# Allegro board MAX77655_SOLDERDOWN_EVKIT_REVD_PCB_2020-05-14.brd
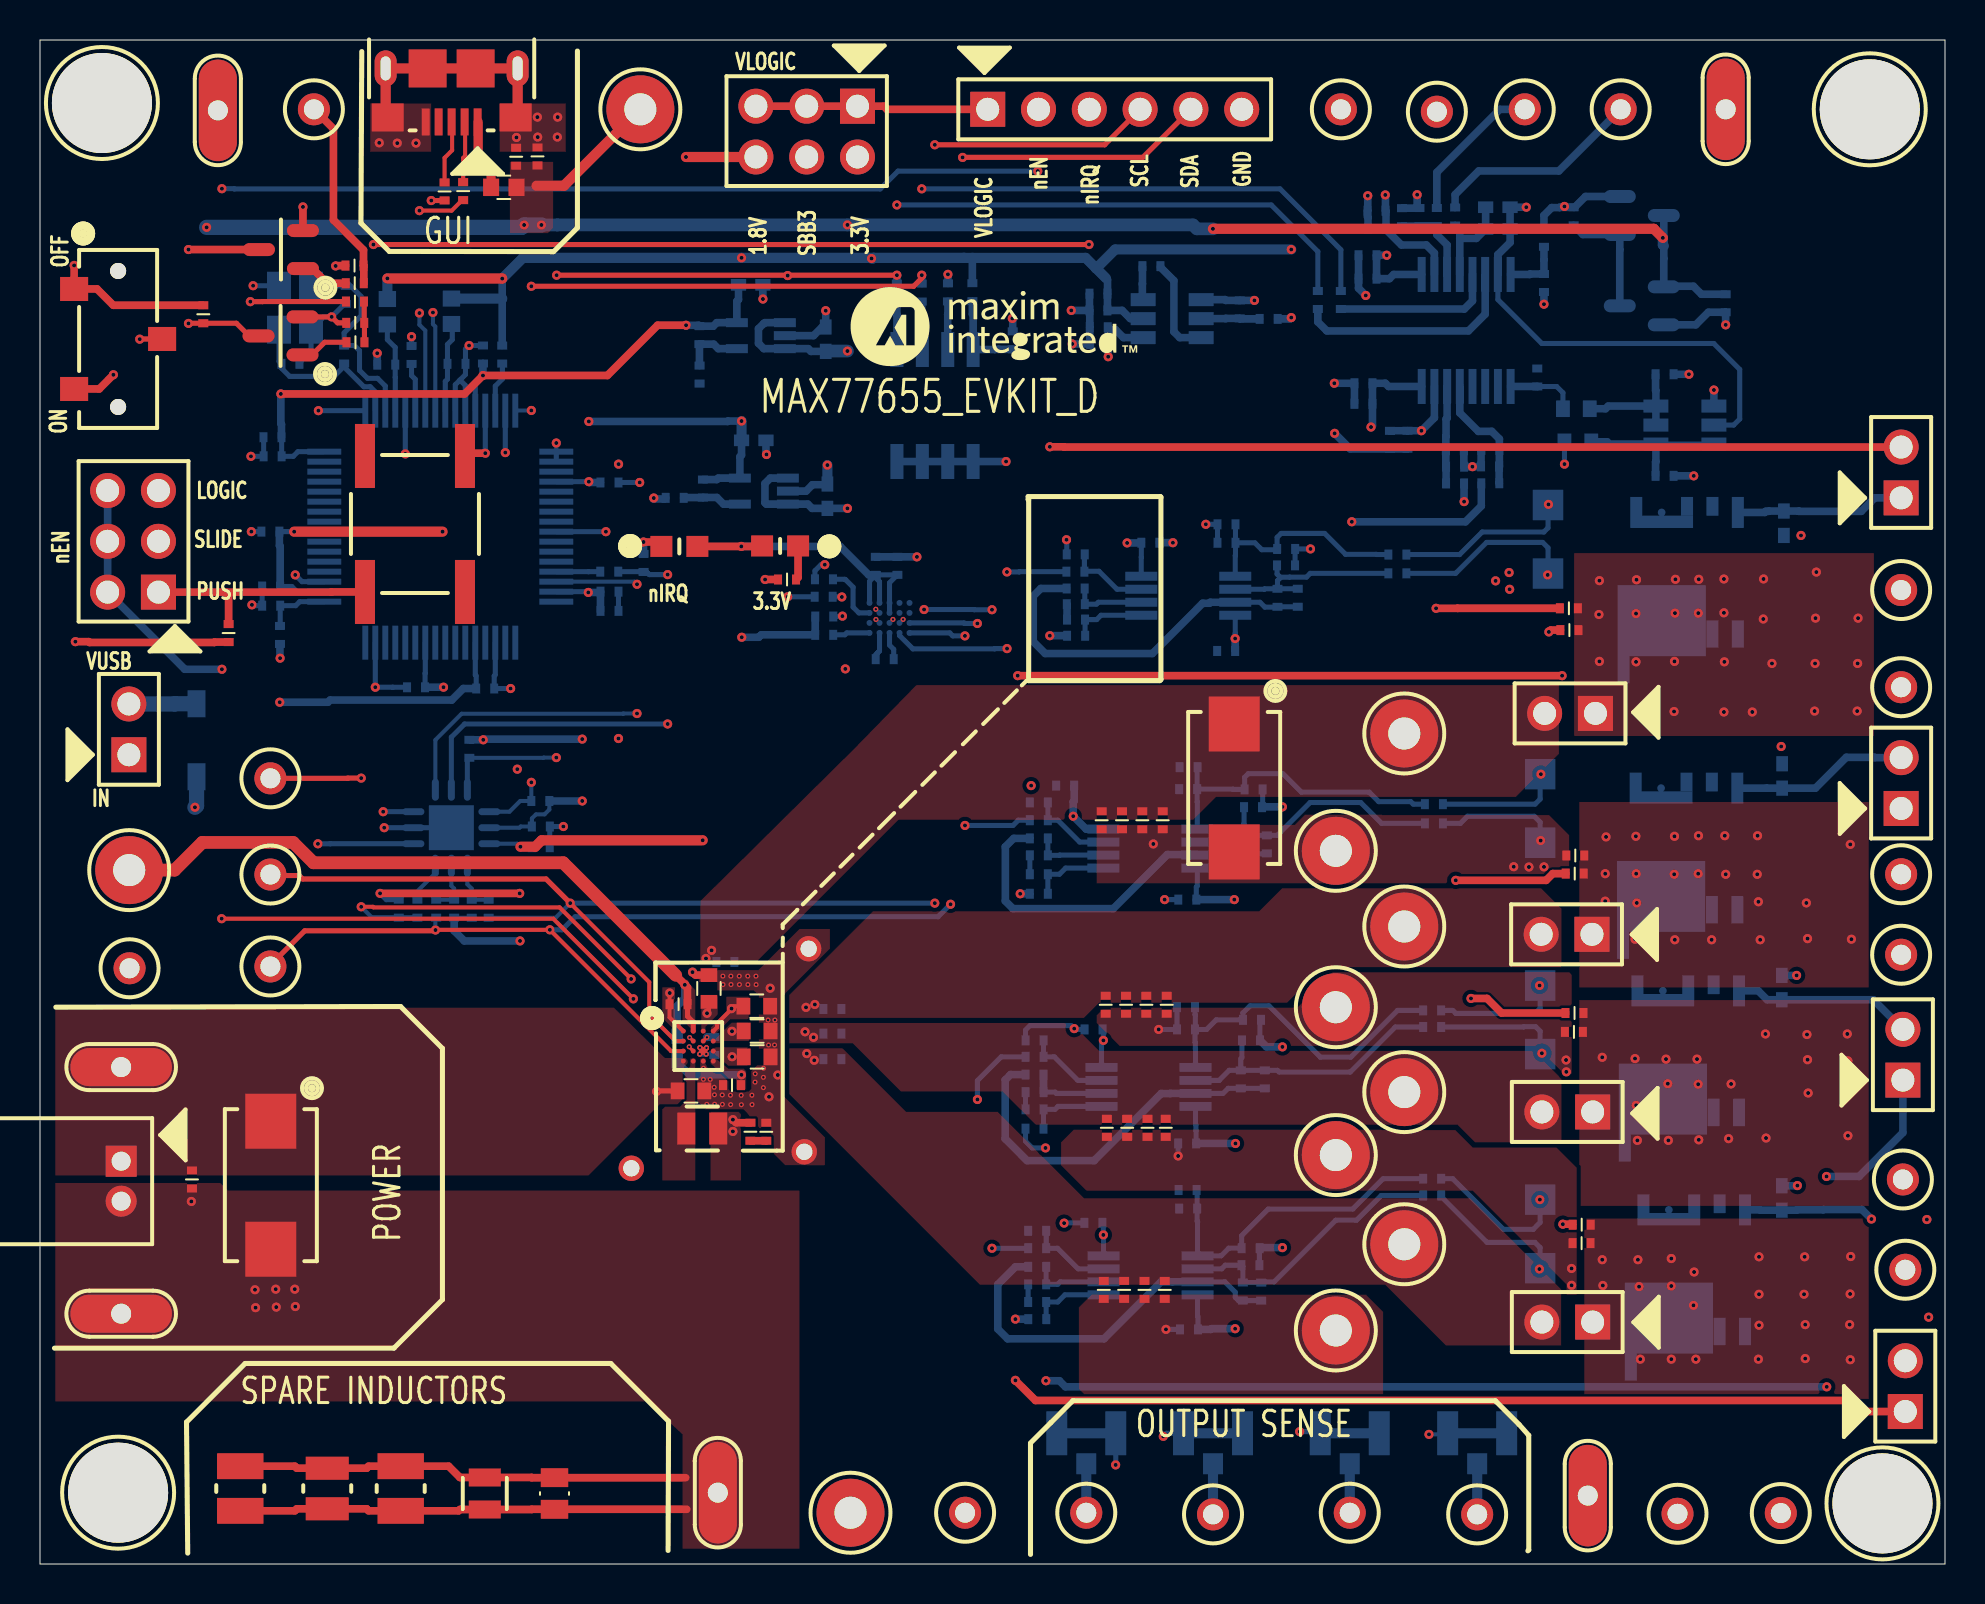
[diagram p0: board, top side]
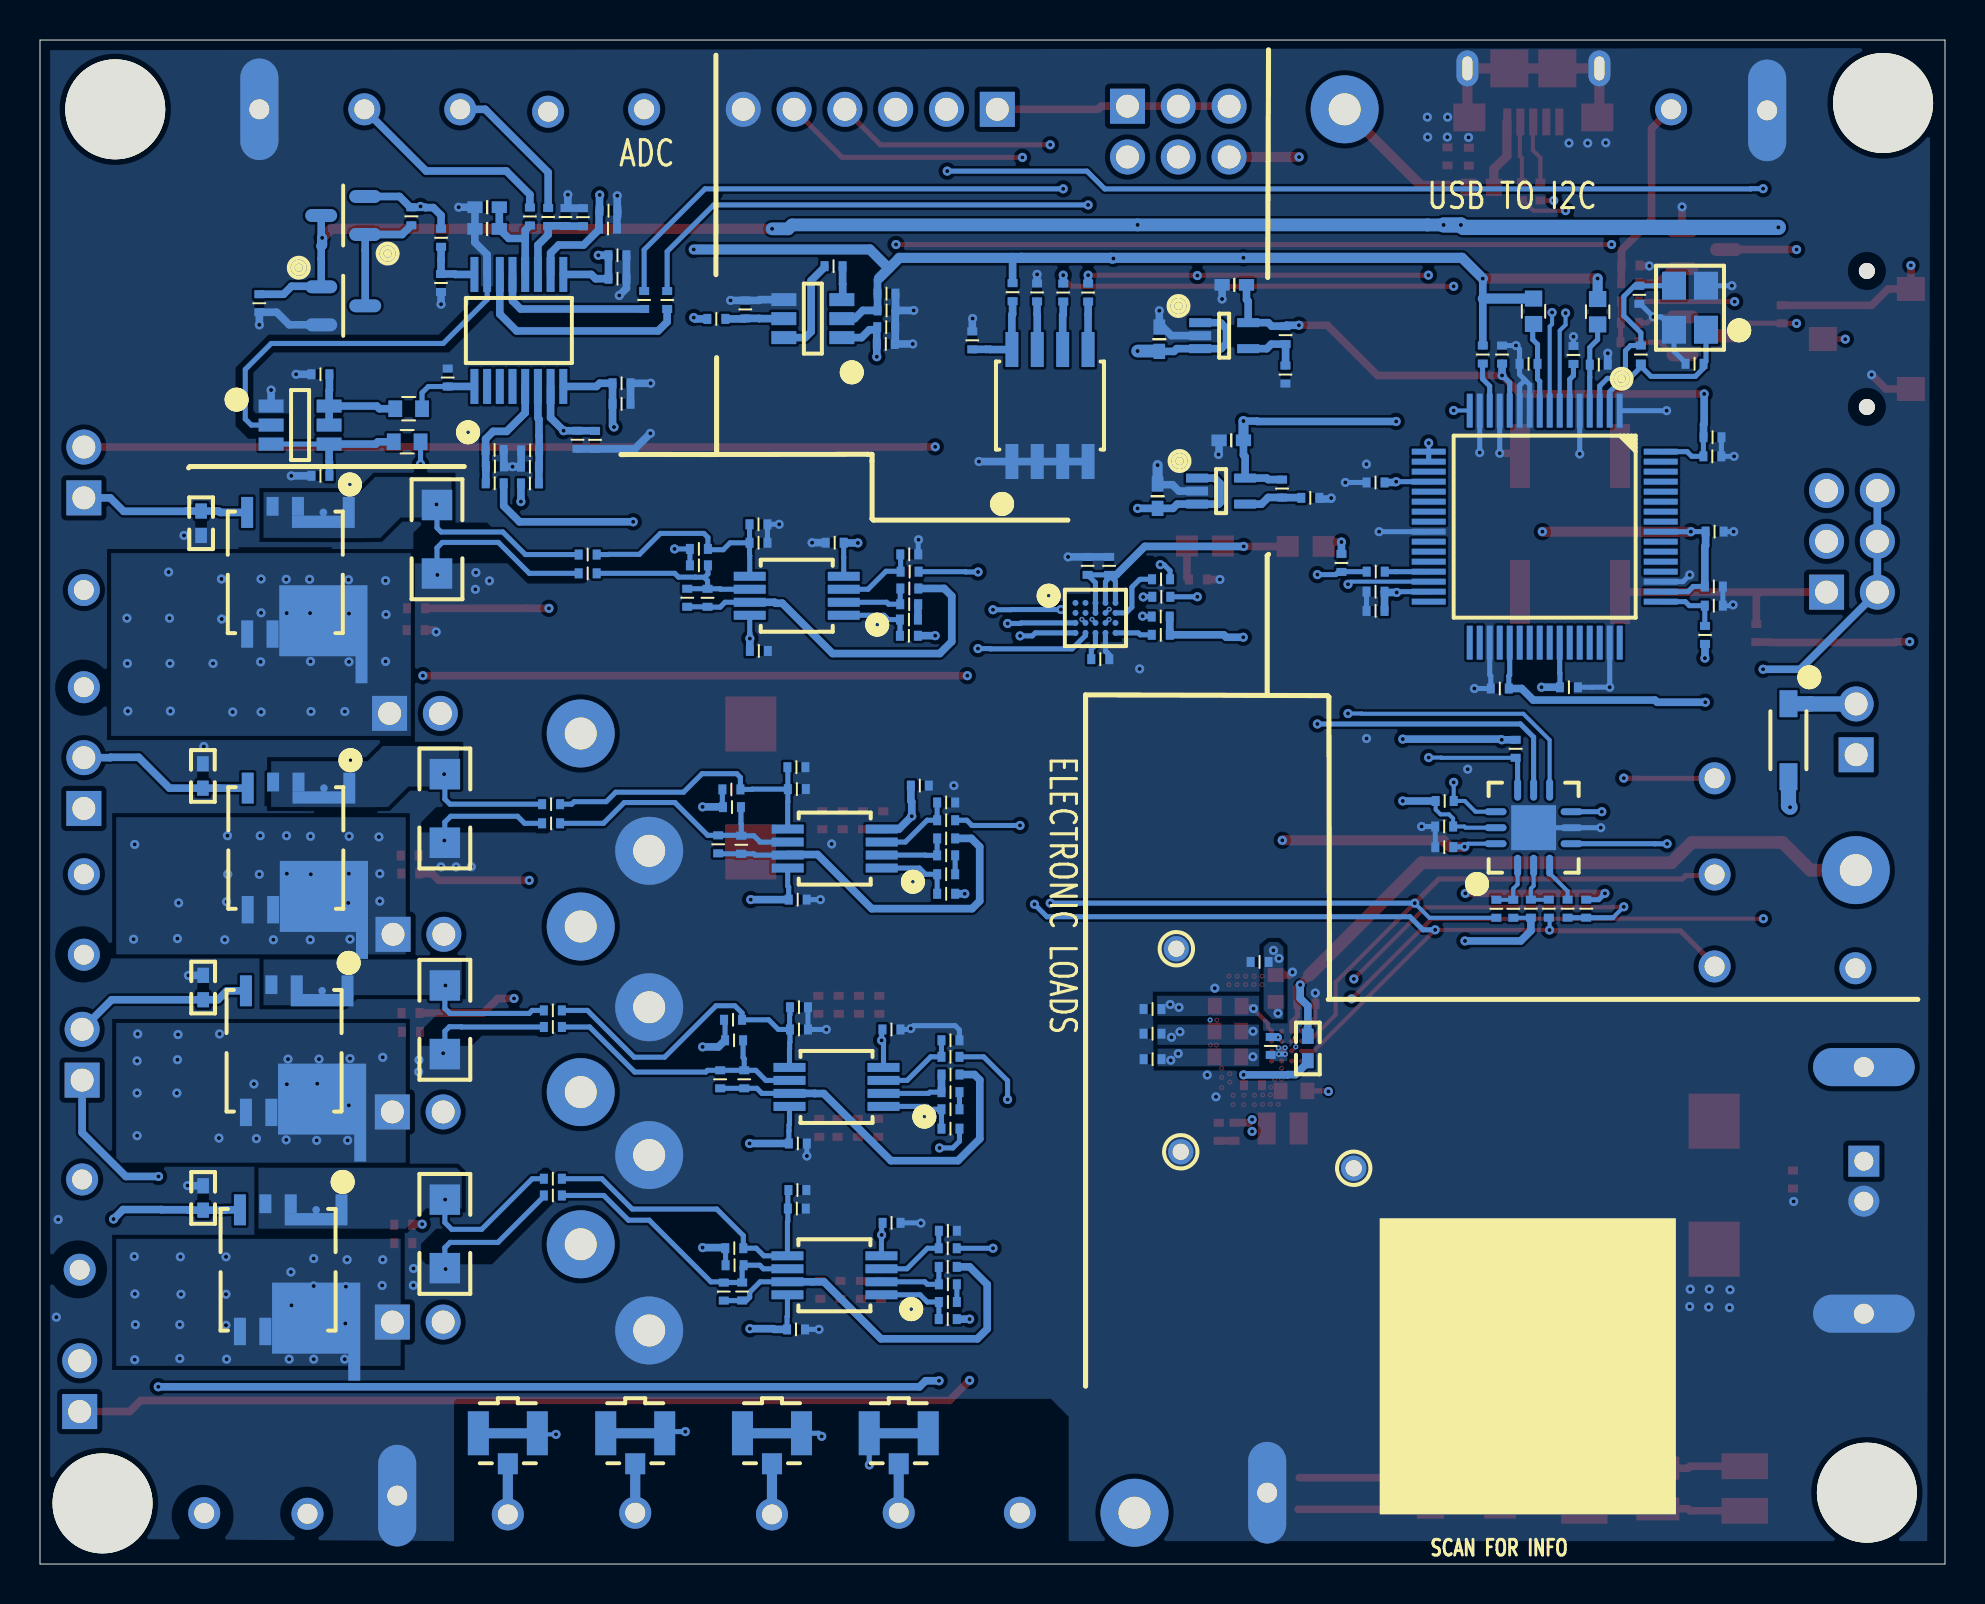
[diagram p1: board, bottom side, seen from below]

Outline 95.25 x 76.2 mm; copper layers: TOP, INTERNAL2, INTERNAL3, BOTTOM. Coordinates in mm from the lower left corner of the outline.
Outline path: 0,76.2 0,0 95.25,0 95.25,76.2 0,76.2

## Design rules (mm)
constraint set DEFAULT: min track width 0.102

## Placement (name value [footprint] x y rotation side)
AIN0  N/A  [KEYS_5002]  65.04 72.73 0 top
AIN1  N/A  [KEYS_5002]  69.84 72.61 0 top
AIN6  N/A  [KEYS_5002]  74.24 72.73 0 top
AIN7  N/A  [KEYS_5002]  79.03 72.73 0 top
B0_S  U.FL-R-SMT-1  [HRS_UFL-R-SMT-1]  71.86 6.54 180 bottom
B0_SNS  N/A  [KEYS_5000]  71.86 2.48 0 top
B1_S  U.FL-R-SMT-1  [HRS_UFL-R-SMT-1]  65.49 6.54 180 bottom
B1_SNS  N/A  [KEYS_5000]  65.49 2.56 0 top
B2_S  U.FL-R-SMT-1  [HRS_UFL-R-SMT-1]  58.65 6.54 180 bottom
B2_SNS  N/A  [KEYS_5000]  58.65 2.48 0 top
B3_S  U.FL-R-SMT-1  [HRS_UFL-R-SMT-1]  52.31 6.54 180 bottom
B3_SNS  N/A  [KEYS_5000]  52.31 2.56 0 top
C1  0.1UF  [0402]  7.6 19.23 90 top
C2  100UF  [CAPMP7343X430M]  11.54 18.94 270 top
C3  10UF  [0402]  34.6 23.94 0 top
C4  0.01UF  [0402]  33.71 25.9 270 bottom
C5  22UF  [CAPC1608X90L]  32.55 23.66 180 top
C6  22UF  [0603]  35.86 25.36 180 top
C7  4700PF  [0402]  72.52 55.7 0 bottom
C8  47UF  [0603]  35.85 26.65 180 top
C9  4700PF  [0402]  68.1 67.34 270 bottom
C10  1UF  [0402]  31.93 27.99 0 top
C11  47UF  [0603]  35.84 27.89 180 top
C12  100UF  [CAPMP7343X430M]  59.71 38.8 270 top
C13  OPEN  [CAPC1005X50L]  39.62 25.24 180 bottom
C14  22UF  [0603]  33.45 28.78 270 top
C15  OPEN  [CAPC1005X50L]  34.27 30.1 180 bottom
C16  1UF  [0402]  25.04 36.87 180 bottom
C17  OPEN  [CAPC1005X50L]  39.62 27.75 180 bottom
C18  OPEN  [CAPC1005X50L]  39.62 26.52 180 bottom
C19  1500PF  [0402]  36.31 21.61 270 top
C21  4.7UF  [0402]  24.87 70.38 270 top
C22  0.1UF  [0402]  23.81 70.36 270 top
C23  27PF  [0402]  12.52 60.01 180 bottom
C24  27PF  [0402]  15.28 63.46 90 bottom
C25  0.1UF  [0402]  11.56 48.88 0 bottom
C26  0.1UF  [0402]  17.31 59.97 0 bottom
C27  0.1UF  [0402]  20.82 60.01 180 bottom
C28  4.7UF  [0402]  11.56 47.92 0 bottom
C29  1UF  [0402#2]  39.29 61.24 270 bottom
C30  0.1UF  [0402]  22.15 60.47 270 bottom
C31  4.7UF  [0402]  28.47 47.65 180 bottom
C32  0.1UF  [0402]  11.63 55.38 0 bottom
C33  0.1UF  [0402]  11.52 51.62 0 bottom
C34  0.1UF  [0402]  11.62 56.34 0 bottom
C35  0.1UF  [0402]  18.8 43.84 0 bottom
C36  1UF  [0402#2]  35.53 63.96 180 bottom
C37  0.1UF  [0402]  22.26 43.77 180 bottom
C38  0.1UF  [0402]  28.47 48.62 180 bottom
C39  0.1UF  [0402]  28.47 54.08 180 bottom
C41  1UF  [0402#2]  39.37 53.39 270 bottom
C42  1UF  [0402#2]  35.69 56.18 180 bottom
C44  0.1UF  [0402]  25.04 35.84 180 bottom
C53  OPEN  [CAPC1005X50L]  53.34 21.81 90 top
C54  OPEN  [CAPC1005X50L]  53.19 13.71 90 top
C56  OPEN  [CAPC1005X50L]  53.08 37.19 90 top
C57  OPEN  [CAPC1005X50L]  53.29 27.96 90 top
C58  OPEN  [CAPC1005X50L]  54.36 21.81 90 top
C59  OPEN  [CAPC1005X50L]  54.21 13.71 90 top
C61  OPEN  [CAPC1005X50L]  54.1 37.19 90 top
C62  OPEN  [CAPC1005X50L]  54.3 27.96 90 top
C63  0.1UF  [CAPC1005X50L]  55.22 13.71 90 top
C65  0.1UF  [CAPC1005X50L]  55.12 37.19 90 top
C66  0.1UF  [CAPC1005X50L]  55.32 27.96 90 top
C67  0.1UF  [CAPC1005X50L]  55.37 21.81 90 top
C68  0.01UF  [CAPC1005X50L]  56.13 37.19 90 top
C69  0.01UF  [CAPC1005X50L]  56.24 13.71 90 top
C71  0.01UF  [CAPC1005X50L]  56.33 27.96 90 top
C72  0.01UF  [CAPC1005X50L]  56.29 21.81 90 top
C73  0.1UF  [0402]  48.64 61.18 270 bottom
C200  4700PF  [0402]  51.79 50.48 0 bottom
C201  0.01UF  [CAPC1005X50L]  51.79 47.99 180 bottom
C202  0.1UF  [CAPC1005X50L]  59.31 45.65 180 bottom
C203  1000PF  [0402]  61.87 48.31 90 bottom
C204  1000PF  [0402]  59.32 51.06 0 bottom
C205  4700PF  [0402]  68.38 56.21 90 bottom
C206  0.01UF  [CAPC1005X50L]  49.94 35.43 180 bottom
C207  0.1UF  [CAPC1005X50L]  57.36 33.22 180 bottom
C208  1000PF  [0402]  57.41 38.74 0 bottom
C209  1000PF  [0402]  61.34 35.98 90 bottom
C210  4700PF  [0402]  66.17 58.01 0 bottom
C211  0.01UF  [CAPC1005X50L]  49.73 23.59 180 bottom
C212  0.1UF  [CAPC1005X50L]  57.36 21.03 180 bottom
C213  1000PF  [0402]  60.04 24.23 90 bottom
C214  1000PF  [0402]  57.3 26.73 0 bottom
C215  4700PF  [0402]  66.38 65.44 0 bottom
C216  0.01UF  [CAPC1005X50L]  49.86 13.98 180 bottom
C217  0.1UF  [CAPC1005X50L]  57.45 11.73 180 bottom
C218  1000PF  [0402]  57.41 17.77 0 bottom
C219  1000PF  [0402]  60.14 13.62 90 bottom
C220  4700PF  [0402]  66.85 66.77 0 bottom
C221  0.1UF  [CAPC1005X50L]  41.79 49.91 270 bottom
C222  0.1UF  [CAPC1005X50L]  42.87 49.91 270 bottom
C223  0.1UF  [CAPC1005X50L]  42.24 45.24 0 bottom
C234  0.1UF  [0402]  81.23 54.41 180 bottom
C235  0.1UF  [0402]  81.23 59.49 180 bottom
C237  0.1UF  [CAPC1005X50L]  75.2 64.05 90 bottom
C238  4700PF  [0402#2]  72.89 67.84 180 bottom
C239  1UF  [CAPC1005X50L]  76.47 46.7 0 top
C240  1UF  [CAPC1005X50L]  76.76 35.42 0 top
C241  1UF  [CAPC1005X50L]  76.7 26.6 0 top
C242  1UF  [CAPC1005X50L]  77.08 16.04 0 top
C244  0.1UF  [CAPC1005X50L]  74.86 59.32 270 bottom
C248  4700PF  [0402]  49.94 38.08 0 bottom
C250  4700PF  [0402]  49.73 26.19 0 bottom
C251  4700PF  [0402]  49.86 16.66 0 bottom
C252  4700PF  [0402]  70.74 55.69 180 bottom
C268  0.1UF  [CAPC1005X50L]  52.93 63.52 0 bottom
C269  1UF  [CAPC1005X50L]  52.92 62.68 0 bottom
C270  1UF  [CAPC1005X50L]  55.57 64.89 0 bottom
C271  1UF  [CAPC1005X50L]  52.94 61.84 0 bottom
C272  0.1UF  [CAPC1005X50L]  52.96 61 0 bottom
C273  0.1UF  [CAPC1005X50L]  59.99 62.73 270 bottom
C274  0.1UF  [CAPC1005X50L]  55.52 51.06 180 bottom
C275  0.1UF  [CAPC1005X50L]  51.26 38.92 0 bottom
C276  0.1UF  [CAPC1005X50L]  52.68 26.73 0 bottom
C277  0.1UF  [CAPC1005X50L]  52.67 17.06 0 bottom
D1  B0530W  [SOD3718X145M]  7.83 41.19 270 bottom
DS1  LTST-C190CKT  [LEDC1608X80M]  31.97 50.88 0 top
DS2  LTST-C190CKT  [LEDC1608X80M]  37 50.9 180 top
GND1  N/A  [KEYS_5011]  64.79 27.84 0 top
GND2  MAXIMPAD  [EVK_MAXIMPAD]  4.06 12.51 180 top
GND3  MAXIMPAD  [EVK_MAXIMPAD]  8.89 72.68 90 top
GND4  MAXIMPAD  [EVK_MAXIMPAD]  84.28 72.73 270 top
GND5  N/A  [KEYS_5011]  64.79 35.66 0 top
GND6  N/A  [KEYS_5011]  64.79 20.45 0 top
GND7  N/A  [KEYS_5011]  64.79 11.68 0 top
GND8  MAXIMPAD  [EVK_MAXIMPAD]  77.39 3.42 90 top
GND10  MAXIMPAD  [EVK_MAXIMPAD]  33.89 3.57 90 top
GND_SNS  N/A  [KEYS_5001]  46.25 2.56 0 top
GNDS1  NA  [TP_C127H81]  29.57 19.79 180 bottom
GNDS2  NA  [TP_C127H81]  38.43 30.76 180 bottom
GNDS3  NA  [TP_C127H81]  38.21 20.61 180 bottom
GNDS_SBB0  N/A  [KEYS_5001]  93.06 43.84 0 top
GNDS_SBB1  N/A  [KEYS_5001]  93.06 30.46 0 top
GNDS_SBB2  N/A  [KEYS_5001]  93.27 14.71 0 top
GNDS_SBB3  N/A  [KEYS_5001]  81.88 2.51 0 top
IN  MAXIMPAD  [EVK_MAXIMPAD]  4.06 24.85 0 top
IN_SNS  N/A  [KEYS_5000]  4.48 29.79 0 top
J1  10118193-0001LF  [FCI_10118193-0001LF]  20.58 74.78 180 top
J2  PBC06SAAN  [SULLINS_PXC06SAAN]  47.39 72.73 0 top
J3  PBC03DAAN  [SULLINS_PXC03DAAN]  5.92 48.59 90 top
J4  PBC03DAAN  [SULLINS_PXC03DAAN]  40.87 72.89 180 top
J5  TSW-102-07-T-S  [SAMTEC_TSW-102-07-X-S]  4.44 40.46 90 top
J9  S2B-PH-K-S(LF)(SN)  [JST_S2B-PH-K-X]  4.06 20.14 90 top
J200  TSW-102-07-T-S  [SAMTEC_TSW-102-07-X-S]  93.06 53.31 90 top
J201  TSW-102-07-T-S  [SAMTEC_TSW-102-07-X-S]  77.77 42.53 180 top
J202  TSW-102-07-T-S  [SAMTEC_TSW-102-07-X-S]  93.06 37.78 90 top
J203  TSW-102-07-T-S  [SAMTEC_TSW-102-07-X-S]  77.6 31.48 180 top
J204  TSW-102-07-T-S  [SAMTEC_TSW-102-07-X-S]  93.14 24.19 90 top
J205  TSW-102-07-T-S  [SAMTEC_TSW-102-07-X-S]  77.63 22.6 180 top
J206  TSW-102-07-T-S  [SAMTEC_TSW-102-07-X-S]  93.27 7.62 90 top
J207  TSW-102-07-T-S  [SAMTEC_TSW-102-07-X-S]  77.63 12.1 180 top
L1  1.5UH  [IND_2016]  33.11 21.77 180 top
L2  600  [0603#2]  23.19 68.83 0 top
L3  1.5UH  [0805]  25.73 3.53 270 top
L4  600  [0603#2]  20.57 62.64 270 bottom
L5  600  [0603#2]  17.37 62.61 270 bottom
L6  1.5UH  [IND_2016]  22.24 3.53 90 top
L7  1UH  [INDC2520X120M]  18.03 3.77 90 top
L8  2.2UH  [IND_2520]  14.36 3.77 270 top
L9  2.2UH  [INDC2520X120M]  10.01 3.77 270 top
NEN_EXT  N/A  [KEYS_5002]  13.69 72.73 0 top
NIRQ  N/A  [KEYS_5002]  11.52 39.28 0 top
NOREF  -  []  12.7 -12.7 0 top
NOREF#2  -  [unnamed#2]  3.91 3.57 0 top
NOREF#3  -  [unnamed#2]  92.12 3.03 0 top
NOREF#4  -  [unnamed#2]  3.1 73.05 0 top
NOREF#5  -  []  38.94 48.61 0 top
NOREF#6  -  []  42.55 61.79 0 top
NOREF#7  -  []  0 76.2 0 top
NOREF#8  -  []  45.62 129.01 0 top
NOREF#9  -  []  0 0 90 top
NOREF#10  -  [unnamed#2]  91.49 72.73 0 top
NOREF#11  -  []  28.26 2.48 180 bottom
PVDD  N/A  [KEYS_5010]  40.53 2.56 0 top
Q1  BSS138  [SOT95P237X112-3M]  12.03 61.41 180 top
Q2  BSS138  [SOT95P237X112-3M]  12.05 65.72 180 top
Q200  IPC100N04S5L1R1ATMA1  [TRANS_PG-TDSON-8-34]  82.99 49.58 0 bottom
Q201  IPC100N04S5L1R1ATMA1  [TRANS_PG-TDSON-8-34]  82.96 35.8 0 bottom
Q202  IPC100N04S5L1R1ATMA1  [TRANS_PG-TDSON-8-34]  83.05 25.66 0 bottom
Q203  IPC100N04S5L1R1ATMA1  [TRANS_PG-TDSON-8-34]  83.35 14.71 0 bottom
Q205  FDN360P  [SOT95P237X112-3M]  80.09 67.43 0 bottom
Q206  2N7002  [SOT95P237X112-3M]  80.09 62.91 180 bottom
R1  0  [RESC1005X50L]  72.51 54.03 0 bottom
R2  10K  [0402]  69.84 67.35 270 bottom
R3  10M  [0402]  15.76 62.06 180 top
R4  1M  [0402]  72.5 54.88 180 bottom
R5  100K  [RESC1005X50L]  17.94 32.77 270 bottom
R6  10K  [0402]  68.98 67.35 90 bottom
R7  1  [0402]  15.77 61.09 180 top
R8  10M  [0402]  8.16 62.49 270 top
R9  0  [0402#2]  31.86 25.78 90 bottom
R10  27  [0402]  21.16 68.64 270 top
R11  27  [0402]  20.23 68.63 270 top
R12  12K  [0402]  18.58 60.45 270 bottom
R13  1M  [0402]  15.21 60.47 90 bottom
R14  1K  [0402]  23.11 60.47 270 bottom
R15  OPEN  [RESC1005X50L]  12 46.45 90 bottom
R16  47.5K  [0402]  32.97 61.44 270 bottom
R17  100K  [0402]  32.98 59.47 270 bottom
R18  150  [0402]  30.18 50.05 270 bottom
R19  0  [0402]  28.46 49.62 0 bottom
R20  0  [0402]  46.62 63.59 270 bottom
R21  4.7K  [0402]  21.47 40.76 270 bottom
R22  4.7K  [0402]  25.02 38.15 180 bottom
R23  169K  [0402]  33.15 53.77 270 bottom
R24  100K  [0402]  31.73 53.31 180 bottom
R25  2.2K  [0402]  20.71 32.77 90 bottom
R26  2.2K  [0402]  21.59 32.76 90 bottom
R27  22  [0402]  18.87 32.77 270 bottom
R28  470  [0402]  37.35 49.23 180 top
R29  0  [0402]  22.43 32.76 270 bottom
R30  0  [0402]  19.81 32.77 270 bottom
R31  0  [0402]  15.75 63.12 0 top
R32  1  [0402]  15.74 64.04 0 top
R33  10M  [0402]  15.73 64.92 180 top
R34  3.9  [0402]  35.52 21.61 270 top
R37  OPEN  [RESC1005X50L]  9.43 46.55 90 top
R52  0  [0402]  45.4 63.58 270 bottom
R53  0  [0402]  44.09 63.57 90 bottom
R54  0  [0402]  42.84 63.57 90 bottom
R201  100  [0402]  51.8 47.22 0 bottom
R202  680  [0402]  51.78 48.78 180 bottom
R203  20K  [0402]  51.77 49.62 0 bottom
R204  0  [RESC1005X50L]  51.81 46.41 180 bottom
R205  20K  [0402]  62.89 48.31 90 bottom
R206  20K  [0402]  59.33 51.98 0 bottom
R207  1K  [RESC1005X50L]  67.87 50.47 0 bottom
R208  1K  [RESC1005X50L]  67.87 49.53 0 bottom
R210  1M  [0402#2]  87.19 52.04 270 bottom
R211  0.1  [1206]  75.4 51.24 270 bottom
R212  787K  [0402]  76.45 47.78 180 top
R213  787K  [0402]  67.5 56.21 270 bottom
R214  100K  [RESC1005X50L]  39.21 47.37 0 bottom
R222  100  [0402]  49.94 34.49 0 bottom
R223  680  [0402]  49.94 36.28 180 bottom
R224  20K  [0402]  49.94 37.19 0 bottom
R225  0  [RESC1005X50L]  49.94 33.51 180 bottom
R226  20K  [0402]  57.43 39.84 0 bottom
R227  787K  [0402]  76.74 34.52 180 top
R228  20K  [0402]  60.19 35.96 90 bottom
R229  1K  [RESC1005X50L]  69.7 37.99 0 bottom
R230  1K  [RESC1005X50L]  69.7 37.03 0 bottom
R231  1M  [0402#2]  87.11 39.4 90 bottom
R233  0.1  [1206]  75.01 37.78 270 bottom
R234  787K  [0402]  66.17 59.04 180 bottom
R235  100  [0402]  49.73 22.74 0 bottom
R236  680  [0402]  49.72 24.47 180 bottom
R237  20K  [0402]  49.73 25.36 0 bottom
R238  0  [RESC1005X50L]  49.73 21.77 180 bottom
R239  20K  [0402]  61.24 24.23 90 bottom
R240  20K  [0402]  57.3 27.84 0 bottom
R242  1K  [RESC1005X50L]  69.61 27.68 0 bottom
R243  1K  [RESC1005X50L]  69.61 26.85 0 bottom
R244  1M  [0402#2]  87.09 28.82 90 bottom
R245  0.1  [1206]  75.01 27.21 270 bottom
R246  787K  [0402]  76.73 27.55 180 top
R247  787K  [0402]  66.38 64.26 180 bottom
R248  100  [0402]  49.86 13.1 0 bottom
R249  680  [0402]  49.86 14.86 180 bottom
R250  20K  [0402]  49.86 15.79 0 bottom
R251  0  [RESC1005X50L]  49.86 12.24 180 bottom
R252  20K  [0402]  57.38 18.7 0 bottom
R253  20K  [0402]  61.06 13.62 90 bottom
R254  1K  [RESC1005X50L]  69.61 19.26 0 bottom
R255  1K  [RESC1005X50L]  69.61 18.43 0 bottom
R257  1M  [0402#2]  87.09 18.3 90 bottom
R258  0.1  [1206]  75.01 16.51 270 bottom
R259  787K  [0402]  77.09 16.97 180 top
R260  787K  [0402]  66.82 67.67 180 bottom
R277  0  [RESC1608X90L]  76.89 56.11 0 bottom
R279  0  [RESC1608X90L]  76.82 57.76 180 bottom
R281  10K  [0402]  70.76 67.38 270 bottom
R282  10K  [0402#2]  72.9 66.75 0 bottom
R283  100K  [RESC1005X50L]  39.21 46.46 0 bottom
R286  0  [RESC1005X50L]  75.2 66.31 270 bottom
R287  10K  [0402]  84.28 63.04 270 bottom
R288  10K  [0402]  76.68 67.38 270 bottom
R289  100  [0402]  61.43 62.25 180 bottom
R293  470K  [0402]  62.31 50.75 0 bottom
R294  649K  [0402]  62.3 49.93 180 bottom
R295  470K  [0402]  60.68 38.73 0 bottom
R296  649K  [0402]  60.65 37.84 180 bottom
R297  470K  [0402]  60.6 27.21 0 bottom
R298  649K  [0402]  60.55 26.19 180 bottom
R299  470K  [0402]  60.54 15.79 0 bottom
R300  649K  [0402]  60.52 14.94 180 bottom
R301  1M  [0402]  70.76 54.87 0 bottom
R302  0  [RESC1005X50L]  70.75 54.03 180 bottom
R303  0  [RESC1005X50L]  63.89 63.2 270 bottom
R304  0  [RESC1005X50L]  65.04 63.2 270 bottom
R305  0  [RESC1005X50L]  39.18 48.36 0 bottom
R306  0  [RESC1005X50L]  39.2 49.24 0 bottom
SBB0  N/A  [KEYS_5010]  68.21 41.53 0 top
SBB1  N/A  [KEYS_5010]  68.21 31.87 0 top
SBB2  N/A  [KEYS_5010]  68.21 23.59 0 top
SBB3  N/A  [KEYS_5010]  68.21 15.99 0 top
SCL  N/A  [KEYS_5002]  11.52 34.47 0 top
SDA  N/A  [KEYS_5002]  11.52 29.88 0 top
SW1  EVQ-Q2K03W  [SW_EVQ-Q2X03W]  18.75 52 90 top
SW2  CL-SB-12B-11  [SW_CL-SB-12B-1X]  3.91 61.25 0 top
U1  MAX77655AEWE+  [MAXIM_21-100374]  32.91 25.9 0 top
U2  FT2232HL  [QFP50P1200X1200X160-64M]  20.02 51.87 270 bottom
U3  MAX8512EXK  [SOT65P210X110-5M]  36.04 61.42 180 bottom
U4  MAX8512EXK  [SOT65P210X110-5M]  36.2 53.64 180 bottom
U5  MAX3395EETC  [QFN80P400X400X80-13M]  20.57 36.82 90 bottom
U7  AT24CS02-SSHM  [SOIC127P600X175-8M]  44.75 57.92 90 bottom
U200  MAX44251AUA+  [SOP65P490X110-8M]  57.41 48.41 0 bottom
U201  MAX44251AUA+  [SOP65P490X110-8M]  55.51 35.77 0 bottom
U202  MAX44251AUA+  [SOP65P490X110-8M]  55.43 23.85 0 bottom
U203  MAX44251AUA+  [SOP65P490X110-8M]  55.53 14.44 0 bottom
U205  MAX5825AWP+T  [BGA20C50P5X4_250X225X64]  42.48 47.3 180 bottom
U209  MAX11614EEE+  [SOP63P600X175-16M]  71.31 61.68 90 bottom
U210  MAX6071AAUT41+  [SOT95P280X145-6M]  82.25 56.95 180 bottom
U211  MAX1697UEUT+  [SOT95P280X145-6M]  56.61 62.27 0 bottom
VDD  N/A  [KEYS_5010]  4.46 34.69 0 top
VIL_SBB0  N/A  [KEYS_5002]  93.06 48.7 0 top
VIL_SBB1  N/A  [KEYS_5002]  93.06 34.49 0 top
VIL_SBB2  N/A  [KEYS_5002]  93.14 19.23 0 top
VIL_SBB3  N/A  [KEYS_5002]  87.04 2.55 0 top
VUSB  N/A  [KEYS_5010]  30.02 72.73 0 top
Y1  12MHZ  [XTAL320X250X080M]  12.75 62.81 90 bottom

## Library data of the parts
AIN0 AIN1 AIN6 AIN7 NEN_EXT NIRQ SCL SDA VIL_SBB0-VIL_SBB3 = TP: part number: TP_TP-KEYS_5002,N/A,02-TPMINI5002-00
B0_S B1_S B2_S B3_S = UFL-R-SMT-1: part number: UFL-R-SMT-1_SMD-HRS_UFL-R-SMT-1,U.FL-R-SMT-1,01-UFLRSMT12P-10
B0_SNS B1_SNS B2_SNS B3_SNS IN_SNS = TP: part number: TP_TP-KEYS_5000,N/A,02-TPMINI5000-00
C1 C234 C235 = CAP_NP: alternate symbols: 0402_NOSILK,CAPC1005X50L,CAP0402-NOT_FOR_TEST; part number: CAP_NP_0402CAP-0402,0.1UF,20-000U1-E2A
C2 = CAP_POL: part number: CAP_POL_7343CAP-CAPMP7343X430M,100UF,20-0100U-P2
C3 = CAP_NP: alternate symbols: 0402_NOSILK,CAPC1005X50L,CAP0402-NOT_FOR_TEST; part number: CAP_NP_0402CAP-0402,10UF,20-0010U-BA12
C4 = CAP_NP: alternate symbols: 0402_NOSILK,CAPC1005X50L,CAP0402-NOT_FOR_TEST; part number: CAP_NP_0402CAP-0402,0.01UF,20-00U01-B60
C5 = EK_CAP_NP: part number: EK_CAP_NP_0603_FF-CAPC1608X90L,22UF,20-0022U-A48
C6 C14 = CAP_NP: alternate symbols: 0603_NOSILK,CAPC1608X90L; part number: CAP_NP_0603CAP-0603,22UF,20-0022U-16S
C7 C9 C200 C205 C210 C215 C220 C238 C248 C250-C252 = CAP_NP: alternate symbols: 0402_NOSILK,CAPC1005X50L,CAP0402-NOT_FOR_TEST; part number: CAP_NP_0402CAP-0402,4700PF,20-4700P-15
C8 C11 = CAP_NP: alternate symbols: 0603_NOSILK,CAPC1608X90L; part number: CAP_NP_0603CAP-0603,47UF,20-0047U-X3
C10 C16 C29 C36 C41 C42 = CAP_NP: alternate symbols: 0402_NOSILK,CAPC1005X50L,CAP0402-NOT_FOR_TEST; part number: CAP_NP_0402CAP-0402,1UF,20-0001U-B8
C12 = CAP_POL: part number: CAP_POL_7343CAP-CAPMP7343X430M,100UF,20-0100U-01
C13 C15 C17 C18 C53 C54 C56-C59 C61 C62 = EK_CAP_NP: alternate symbols: 0402,0402_NOSILK; part number: EK_CAP_NP_0402_FF-CAPC1005X50L,OPEN,N/A
C19 = CAP_NP: alternate symbols: 0402_NOSILK,CAPC1005X50L,CAP0402-NOT_FOR_TEST; part number: CAP_NP_0402CAP-0402,1500PF,20-1500P-14
C21 C28 C31 = CAP_NP: alternate symbols: 0402_NOSILK,CAPC1005X50L; part number: CAP_NP_0402CAP-0402,4.7UF,20-004U7-Z52
C22 C25-C27 C30 C32-C35 C37-C39 C44 C73 = CAP_NP: alternate symbols: 0402_NOSILK,CAPC1005X50L; part number: CAP_NP_0402CAP-0402,0.1UF,20-000U1-30
C23 C24 = CAP_NP: alternate symbols: 0402_NOSILK,CAPC1005X50L,CAP0402-NOT_FOR_TEST; part number: CAP_NP_0402CAP-0402,27PF,20-0027P-27
C63 C65-C67 = EK_CAP_NP: part number: EK_CAP_NP_0402_FF-CAPC1005X50L,0.1UF,20-000U1-33
C68 C69 C71 C72 C201 C206 C211 C216 = EK_CAP_NP: part number: EK_CAP_NP_0402_FF-CAPC1005X50L,0.01UF,20-00U01-B8
C202 C207 C212 C217 C221-C223 C237 C244 C268 C272-C277 = EK_CAP_NP: part number: EK_CAP_NP_0402_FF-CAPC1005X50L,0.1UF,20-000U1-12
C203 C204 C208 C209 C213 C214 C218 C219 = CAP_NP: alternate symbols: 0402_NOSILK,CAPC1005X50L,CAP0402-NOT_FOR_TEST; part number: CAP_NP_0402CAP-0402,1000PF,20-1000P-05
C239-C242 = EK_CAP_NP: part number: EK_CAP_NP_0402_FF-CAPC1005X50L,1UF,20-0001U-B65
C269-C271 = EK_CAP_NP: part number: EK_CAP_NP_0402_FF-CAPC1005X50L,1UF,20-0001U-E2
D1 = DIO_SCHOTTKY: part number: DIO_SCHOTTKY_SOD-123-SOD3718X145M,B0530W,30-B0530W-00
DS1 DS2 = LED: part number: LED_LEDC1608X80M-LEDC1608X80M,LTST-C190CKT,30-LTSTC190CKT-00
GND1 GND5-GND7 = TP: alternate symbols: TP_C340H160L; part number: TP_TP-KEYS_5011,N/A,02-TPMINI5011-00
GND2-GND4 GND8 GND10 IN = EVK_MAXIMPAD: alternate symbols: EVK_MAXIMPAD_ALT; part number: EVK_MAXIMPAD_MISC-EVK_MAXIMPAD,MAXIMPAD,01-9020BUSS20AWG-00
GND_SNS GNDS_SBB0-GNDS_SBB3 = TP: part number: TP_TP-KEYS_5001,N/A,02-TPMINI5001-00
GNDS1-GNDS3 = TP: part number: TP_TP-TP_C127H81,NA,NA
J1 = 10118193-0001LF: part number: 10118193-0001LF_SMD-FCI_10118193-0001LF,10118193-0001LF,01-101181930001LF5P-26
J2 = HEADER_6P: part number: HEADER_6P_TH-SULLINS_PXC06SAAN,PBC06SAAN,01-PBC06SAAN6P-21
J3 J4 = HEADER_3P_X_2R: part number: HEADER_3P_X_2R_TH-SULLINS_PXC03DAAN,PBC03DAAN,01-PBC03DAAN6P-21
J5 J200-J207 = HEADER_2P: part number: HEADER_2P_TH-SAMTEC_TSW-102-07-X-S,TSW-102-07-T-S,01-TSW10207TS2P-17
J9 = HEADER_2P: part number: HEADER_2P_RA-JST_S2B-PH-K-X,S2B-PH-K-S(LF)(SN),01-S2BPHKS2P-19
L1 L6 = INDUCT: alternate symbols: INDC2016X100L; part number: INDUCT_0806-IND_2016,1.5UH,50-001U5-0NK
L2 L4 L5 = FERRITEBEAD: alternate symbols: INDC1608X65L; part number: FERRITEBEAD_0603-0603,600,51-00600-SM2
L3 = INDUCT: alternate symbols: INDC2012X145L; part number: INDUCT_0805-0805,1.5UH,EL111000004338
L7 = INDUCT: part number: INDUCT_2520-INDC2520X120M,1UH,EL111000004342
L8 = INDUCT: alternate symbols: INDC2520X120L; part number: INDUCT_2520-IND_2520,2.2UH,EL2027
L9 = INDUCT: part number: INDUCT_2520-INDC2520X120M,2.2UH,EL111000004340
PVDD SBB0-SBB3 VDD VUSB = TP: alternate symbols: TP_C340H160L; part number: TP_TP-KEYS_5010,N/A,02-TPMINI5010-00
Q1 Q2 = TRAN_NCH_3P: part number: TRAN_NCH_3P_SOT23-SOT95P237X112-3M,BSS138,90-BSS138-16
Q200-Q203 = TRAN_NCH_8P: part number: TRAN_NCH_8P_PG-TDSON-8-34-TRANS_PG-TDSON-8-34,IPC100N04S5L1R1ATMA1,EQ111000004296
Q205 = TRAN_PCH_3P: part number: TRAN_PCH_3P_SOT-23-SOT95P237X112-3M,FDN360P,90-FDC360P-25
Q206 = TRAN_NCH_3P: part number: TRAN_NCH_3P_SOT23-SOT95P237X112-3M,2N7002,90-2N7002-06
R1 R204 R225 R238 R251 R286 R302-R306 = EK_RES_SMD: part number: EK_RES_SMD_0402_FF-RESC1005X50L,0,80-0000R-26
R2 R6 = RES: alternate symbols: (0402_NOSILK,RESC1005X50L); part number: RES_0402RES-0402,10K,80-0010K-Q6
R3 R8 R33 = RES: alternate symbols: (0402_NOSILK,RESC1005X50L); part number: RES_0402RES-0402,10M,80-0010M-23
R4 R13 R210 R231 R244 R257 R301 = RES: alternate symbols: (0402_NOSILK,RESC1005X50L); part number: RES_0402RES-0402,1M,80-0001M-23
R5 R214 R283 = EK_RES_SMD: part number: EK_RES_SMD_0402_FF-RESC1005X50L,100K,80-0100K-23
R7 R32 = RES: alternate symbols: 0402_NOSILK,RESC1005X50L,RES0402-NOT_FOR_TEST; part number: RES_0402RES-0402,1,80-0001R-23
R9 R19 R20 R29-R31 R52-R54 = RES: alternate symbols: 0402_NOSILK,RESC1005X50L,RES0402-NOT_FOR_TEST; part number: RES_0402RES-0402,0,80-0000R-26A
R10 R11 = RES: alternate symbols: (0402_NOSILK,RESC1005X50L); part number: RES_0402RES-0402,27,80-0027R-23
R12 = RES: alternate symbols: (0402_NOSILK,RESC1005X50L); part number: RES_0402RES-0402,12K,80-0012K-23
R14 = RES: alternate symbols: 0402_NOSILK,RESC1005X50L,RES0402-NOT_FOR_TEST; part number: RES_0402RES-0402,1K,80-0001K-23
R15 R37 = EK_RES_SMD: alternate symbols: 0402,0402_NOSILK,; part number: EK_RES_SMD_0402_FF-RESC1005X50L,OPEN,N/A
R16 = RES: alternate symbols: (0402_NOSILK,RESC1005X50L); part number: RES_0402RES-0402,47.5K,80-047K5-23
R17 R24 = RES: alternate symbols: 0402_NOSILK,RESC1005X50L; part number: RES_0402RES-0402,100K,80-0100K-23
R18 = RES: alternate symbols: (0402_NOSILK,RESC1005X50L); part number: RES_0402RES-0402,150,80-0150R-23
R21 R22 = RES: alternate symbols: (0402_NOSILK,RESC1005X50L); part number: RES_0402RES-0402,4.7K,80-004K7-23
R23 = RES: alternate symbols: (0402_NOSILK,RESC1005X50L); part number: RES_0402RES-0402,169K,80-0169K-23
R25 R26 = RES: alternate symbols: (0402_NOSILK,RESC1005X50L); part number: RES_0402RES-0402,2.2K,80-002K2-23
R27 = RES: alternate symbols: (0402_NOSILK,RESC1005X50L); part number: RES_0402RES-0402,22,80-0022R-23
R28 = RES: alternate symbols: (0402_NOSILK,RESC1005X50L); part number: RES_0402RES-0402,470,80-0470R-23
R34 = RES: alternate symbols: (0402_NOSILK,RESC1005X50L); part number: RES_0402RES-0402,3.9,80-003R9-23
R201 R222 R235 R248 R289 = RES: alternate symbols: 0402_NOSILK,RESC1005X50L,RES0402-NOT_FOR_TEST; part number: RES_0402RES-0402,100,80-0100R-23
R202 R223 R236 R249 = RES: alternate symbols: (0402_NOSILK,RESC1005X50L); part number: RES_0402RES-0402,680,80-0680R-23
R203 R224 R237 R250 = RES: alternate symbols: 0402_NOSILK,RESC1005X50L,RES0402-NOT_FOR_TEST; part number: RES_0402RES-0402,20K,80-0020K-23
R205 R206 R226 R228 R239 R240 R252 R253 = RES: alternate symbols: 0402_NOSILK,RESC1005X50L,RES0402-NOT_FOR_TEST; part number: RES_0402RES-0402,20K,80-0020K-AA23
R207 R208 R229 R230 R242 R243 R254 R255 = EK_RES_SMD: part number: EK_RES_SMD_0402_FF-RESC1005X50L,1K,80-0001K-23
R211 R233 R245 R258 = RES: part number: RES_1206RES-1206,0.1,80-000R1-26
R212 R213 R227 R234 R246 R247 R259 R260 = RES: alternate symbols: (0402_NOSILK,RESC1005X50L); part number: RES_0402RES-0402,787K,80-0787K-23
R277 R279 = EK_RES_SMD: part number: EK_RES_SMD_0603_FF-RESC1608X90L,0,80-0000R-27
R281 R282 R287 R288 = RES: alternate symbols: 0402_NOSILK,RESC1005X50L,RES0402-NOT_FOR_TEST; part number: RES_0402RES-0402,10K,80-0010K-23
R293 R295 R297 R299 = RES: alternate symbols: (0402_NOSILK,RESC1005X50L); part number: RES_0402RES-0402,470K,80-0470K-23
R294 R296 R298 R300 = RES: alternate symbols: 0402_NOSILK,RESC1005X50L; part number: RES_0402RES-0402,649K,80-0649K-AA18
SW1 = EVQ-Q2XXXX: part number: EVQ-Q2XXXX_SMT-SW_EVQ-Q2X03W,EVQ-Q2K03W,11-EVQQ2K03W-00
SW2 = CL-SB-12B-1X: part number: CL-SB-12B-1X_SMD-SW_CL-SB-12B-1X,CL-SB-12B-11,11-CLSB12B11-00
U1 = EK_MAX77655: part number: EK_MAX77655_WLP16-MAXIM_21-100374,MAX77655AEWE+,N/A
U2 = FT2232H: part number: FT2232H_LQFP64-QFP50P1200X1200X160-64M,FT2232HL,10-FT2232HL-C
U3 U4 = MAX8512: part number: MAX8512_SC70-SOT65P210X110-5M,MAX8512EXK,10-MAX8512EXK-X
U5 = MAX3395E: part number: MAX3395E_TQFN-QFN80P400X400X80-13M,MAX3395EETC,10-MAX3395EETC-T
U7 = AT24CS02: part number: AT24CS02_NSOIC8-SOIC127P600X175-8M,AT24CS02-SSHM,EQ111000001211
U200-U203 = MAX44251: part number: MAX44251_SPLIT_UMAX8-SOP65P490X110-8M,MAX44251AUA+,10-MAX44251AUA-U
U205 = MAX5825: part number: MAX5825_WLP20-BGA20C50P5X4_250X225X64,MAX5825AWP+T,10-MAX5825AWP-W
U209 = MAX11614: part number: MAX11614_QSOP16-SOP63P600X175-16M,MAX11614EEE+,10-MAX11614EEE-U
U210 = MAX6071: part number: MAX6071_SOT23-6-SOT95P280X145-6M,MAX6071AAUT41+,10-MAX6071AAUT41-U
U211 = MAX1697: part number: MAX1697_SOT23-6-SOT95P280X145-6M,MAX1697UEUT+,10-MAX1697UEUT-U
Y1 = XTAL: part number: XTAL_XTAL320X250X080M-XTAL320X250X080M,12MHZ,60-0012M-0AI

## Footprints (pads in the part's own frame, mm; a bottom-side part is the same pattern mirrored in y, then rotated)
0402
  rect 0.4x0.5 smd: 1(-0.45,0) 2(0.45,0)
0402#2
  rect 0.762x0.584 smd: 1(-0.61,0) 2(0.61,0)
0603
  rect 0.69x0.83 smd: 1(-0.67,0) 2(0.67,0)
0603#2
  rect 0.8x0.87 smd: 1(-0.635,0) 2(0.635,0)
0805
  rect 0.94x1.37 smd: 1(-0.79,0) 2(0.79,0)
1206
  rect 1.524x1.524 smd: 1(-1.714,0) 2(1.714,0)
BGA20C50P5X4_250X225X64
  round 0.3 smd: A1(-1,0.75) A2(-0.5,0.75) A3(0,0.75) A4(0.5,0.75) A5(1,0.75) B1(-1,0.25) B2(-0.5,0.25) B3(0,0.25) B4(0.5,0.25) B5(1,0.25) C1(-1,-0.25) C2(-0.5,-0.25) C3(0,-0.25) C4(0.5,-0.25) C5(1,-0.25) D1(-1,-0.75) D2(-0.5,-0.75) D3(0,-0.75) D4(0.5,-0.75) D5(1,-0.75)
CAPC1005X50L
  rect 0.4x0.5 smd: 1(-0.45,0) 2(0.45,0)
CAPC1608X90L
  rect 0.69x0.83 smd: 1(-0.67,0) 2(0.67,0)
CAPMP7343X430M
  rect 2.75x2.55 smd: 1(-3.2,0) 2(3.2,0)
EVK_MAXIMPAD
  oval 5.08x1.905 hole 1: 1(0,0)
FCI_10118193-0001LF
  rect 0.4x1.35 smd: 1(-1.3,2.675) 2(-0.65,2.675) 3(0,2.675) 4(0.65,2.675) 5(1.3,2.675)
  rect 1.6x1.4 smd: 6(-3.2,2.45) 7(3.2,2.45)
  rect 1.9x1.9 smd: 8(-1.2,0) 9(1.2,0)
  oval 1.1x1.8 hole 0.5x1.2: 10(-3.3,0) 11(3.3,0)
HRS_UFL-R-SMT-1
  rect 1x1.05 smd: 1(0,-1.525)
  rect 1.05x2.2 smd: 2(-1.475,0) 3(1.475,0)
IND_2016
  rect 0.9x1.6 smd: 1(-0.8,0) 2(0.8,0)
IND_2520
  rect 1.15x2.15 smd: 1(-1.015,0) 2(1.015,0)
INDC2520X120M
  rect 1.29x2.32 smd: 1(-1.115,0) 2(1.115,0)
JST_S2B-PH-K-X
  rect 1.55x1.55 hole 0.95: 1(0,0)
  round 1.55 hole 0.95: 2(-2,0)
KEYS_5000
  round 1.6 hole 1: 1(0,0)
KEYS_5001
  round 1.6 hole 1: 1(0,0)
KEYS_5002
  round 1.6 hole 1: 1(0,0)
KEYS_5010
  round 3.4 hole 1.6: 1(0,0)
KEYS_5011
  round 3.4 hole 1.6: 1(0,0)
LEDC1608X80M
  rect 1.1x1.05 smd: A(0.9,0) K(-0.9,0)
MAXIM_21-100374
  round 0.25 smd: A1(-0.75,0.75) A2(-0.25,0.75) A3(0.25,0.75) A4(0.75,0.75) B1(-0.75,0.25) B2(-0.25,0.25) B3(0.25,0.25) B4(0.75,0.25) C1(-0.75,-0.25) C2(-0.25,-0.25) C3(0.25,-0.25) C4(0.75,-0.25) D1(-0.75,-0.75) D2(-0.25,-0.75) D3(0.25,-0.75) D4(0.75,-0.75)
QFN80P400X400X80-13M
  oval 1.1x0.35 smd: 1(-1.9,0.8) 2(-1.9,0) 3(-1.9,-0.8) 7(1.9,-0.8) 8(1.9,0) 9(1.9,0.8)
  oval 0.35x1.1 smd: 4(-0.8,-1.9) 5(0,-1.9) 6(0.8,-1.9) 10(0.8,1.9) 11(0,1.9) 12(-0.8,1.9)
  rect 2.25x2.25 smd: 13(0,0)
QFP50P1200X1200X160-64M
  rect 1.7x0.3 smd: 1(-5.8,3.75) 2(-5.8,3.25) 3(-5.8,2.75) 4(-5.8,2.25) 5(-5.8,1.75) 6(-5.8,1.25) 7(-5.8,0.75) 8(-5.8,0.25) 9(-5.8,-0.25) 10(-5.8,-0.75) 11(-5.8,-1.25) 12(-5.8,-1.75) 13(-5.8,-2.25) 14(-5.8,-2.75) 15(-5.8,-3.25) 16(-5.8,-3.75) 33(5.8,-3.75) 34(5.8,-3.25) 35(5.8,-2.75) 36(5.8,-2.25) 37(5.8,-1.75) 38(5.8,-1.25) 39(5.8,-0.75) 40(5.8,-0.25) 41(5.8,0.25) 42(5.8,0.75) 43(5.8,1.25) 44(5.8,1.75) 45(5.8,2.25) 46(5.8,2.75) 47(5.8,3.25) 48(5.8,3.75)
  rect 0.3x1.7 smd: 17(-3.75,-5.8) 18(-3.25,-5.8) 19(-2.75,-5.8) 20(-2.25,-5.8) 21(-1.75,-5.8) 22(-1.25,-5.8) 23(-0.75,-5.8) 24(-0.25,-5.8) 25(0.25,-5.8) 26(0.75,-5.8) 27(1.25,-5.8) 28(1.75,-5.8) 29(2.25,-5.8) 30(2.75,-5.8) 31(3.25,-5.8) 32(3.75,-5.8) 49(3.75,5.8) 50(3.25,5.8) 51(2.75,5.8) 52(2.25,5.8) 53(1.75,5.8) 54(1.25,5.8) 55(0.75,5.8) 56(0.25,5.8) 57(-0.25,5.8) 58(-0.75,5.8) 59(-1.25,5.8) 60(-1.75,5.8) 61(-2.25,5.8) 62(-2.75,5.8) 63(-3.25,5.8) 64(-3.75,5.8)
RESC1005X50L
  rect 0.4x0.5 smd: 1(-0.45,0) 2(0.45,0)
RESC1608X90L
  rect 0.69x0.83 smd: 1(-0.67,0) 2(0.67,0)
SAMTEC_TSW-102-07-X-S
  rect 1.75x1.75 hole 1.15: 1(0,0)
  round 1.75 hole 1.15: 2(2.54,0)
SOD3718X145M
  rect 1.35x0.9 smd: A(1.825,0) C(-1.825,0)
SOIC127P600X175-8M
  rect 1.75x0.65 smd: 1(-2.8,1.905) 2(-2.8,0.635) 3(-2.8,-0.635) 4(-2.8,-1.905) 5(2.8,-1.905) 6(2.8,-0.635) 7(2.8,0.635) 8(2.8,1.905)
SOP63P600X175-16M
  rect 1.75x0.4 smd: 1(-2.8,2.223) 2(-2.8,1.588) 3(-2.8,0.953) 4(-2.8,0.318) 5(-2.8,-0.317) 6(-2.8,-0.952) 7(-2.8,-1.587) 8(-2.8,-2.222) 9(2.8,-2.223) 10(2.8,-1.588) 11(2.8,-0.953) 12(2.8,-0.318) 13(2.8,0.317) 14(2.8,0.952) 15(2.8,1.587) 16(2.8,2.222)
SOP65P490X110-8M
  rect 1.6x0.45 smd: 1(-2.35,0.975) 2(-2.35,0.325) 3(-2.35,-0.325) 4(-2.35,-0.975) 5(2.35,-0.975) 6(2.35,-0.325) 7(2.35,0.325) 8(2.35,0.975)
SOT65P210X110-5M
  rect 1.1x0.45 smd: 1(-1.2,0.65) 2(-1.2,0) 3(-1.2,-0.65) 4(1.2,-0.65) 5(1.2,0.65)
SOT95P237X112-3M
  oval 1.6x0.65 smd: 1(-1.1,0.95) 2(-1.1,-0.95) 3(1.1,0)
SOT95P280X145-6M
  rect 1.25x0.65 smd: 1(-1.45,0.95) 2(-1.45,0) 3(-1.45,-0.95) 4(1.45,-0.95) 5(1.45,0) 6(1.45,0.95)
SULLINS_PXC03DAAN
  rect 1.75x1.75 hole 1.15: 1(0,0)
  round 1.75 hole 1.15: 2(0,2.54) 3(2.54,0) 4(2.54,2.54) 5(5.08,0) 6(5.08,2.54)
SULLINS_PXC06SAAN
  rect 1.75x1.75 hole 1.15: 1(0,0)
  round 1.75 hole 1.15: 2(2.54,0) 3(5.08,0) 4(7.62,0) 5(10.16,0) 6(12.7,0)
SW_CL-SB-12B-1X
  round 0.8 hole 0.9 unplated: (0,3.4) (0,-3.4)
  rect 1.4x1.2 smd: 1(-2.2,2.5) 2(2.2,0) 3(-2.2,-2.5)
SW_EVQ-Q2X03W
  rect 3.2x1 smd: 1(-3.4,-2.5) 2(3.4,-2.5) 3(-3.4,2.5) 4(3.4,2.5)
TP_C127H81
  round 1.27 hole 0.813: 1(0,0)
TRANS_PG-TDSON-8-34
  custom 0.387x0.387 smd: 1(-1.905,-2.995)
  rect 0.6x0.94 smd: 2(-0.635,-3.3) 3(0.635,-3.3)
  rect 0.6x1.55 smd: 4(1.905,-2.995)
  rect 0.6x1.37 smd: 5(1.905,3.085) 6(0.635,3.085) 7(-0.635,3.085)
  custom 1.102x1.102 smd: 8(-1.905,3.095)
unnamed#2
  round 5 hole 5 unplated: (0,0)
XTAL320X250X080M
  rect 1.4x1.2 smd: 1(-1.1,-0.8) 2(1.1,-0.8) 3(1.1,0.8) 4(-1.1,0.8)

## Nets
+1.8V: C30.2 C32.2 C34.2 C36.2 C37.2 J4.6 R15.1 R16.1 U2.12 U2.37 U2.64 U3.5
+3.3V: C16.2 C25.2 C31.2 C33.2 C35.2 C38.2 C39.2 C42.2 C221.2 C222.2 C268.2 C269.2 DS1.A DS2.A J4.2 L4.1 L5.1 R14.1 R20.1 R21.1 R22.1 R23.1 R214.1 R283.1 R289.1 R293.2 R294.1 R295.2 R296.1 R297.2 R298.1 R299.2 R300.1 U2.20 U2.31 U2.42 U2.50 U2.56 U4.5 U5.11 U205.A3(VDDIO) U205.A4 U205.A5 U205.B3 U211.2
PVDD: C3.2 PVDD.1(TP1) R9.1 U1.D4
VCC_USB: J1.1 L2.1
VDD: C10.2 R9.2 U1.A2 VDD.1(TP1)
VSS: C271.2 C272.2 C274.2 C275.2 C276.2 C277.2 U200.4 U201.4 U202.4 U203.4 U211.1(OUT)
ADC_REF: C244.2 R279.2 U209.1
ADC_SBB0: C205.2 R212.2 R213.1 U209.7
ADC_SBB1: C210.2 R227.2 R234.1 U209.8
ADC_SBB2: C215.2 R246.2 R247.1 U209.9
ADC_SBB3: C220.2 R259.2 R260.1 U209.10
BST: C4.1 U1.B3
FTDI_DM: R10.2 U2.7
FTDI_DP: R11.2 U2.8
FTDI_OSCI: C23.2 R13.1 U2.2 Y1.1
FTDI_OSCO: C24.2 R13.2 U2.3 Y1.3(P2)
FTDI_REF: R12.2 U2.6
GROUND: B0_S.2 B0_S.3 B1_S.2 B1_S.3 B2_S.2 B2_S.3 B3_S.2 B3_S.3 C1.1 C2.2(B) C3.1 C5.1 C6.1 C7.1 C8.1 C9.1 C10.1 C11.1 C12.2(B) C13.1 C14.1 C15.1 C16.1 C17.1 C18.1 C19.1 C21.1 C22.1 C23.1 C24.1 C25.1 C26.1 C27.1 C28.1 C29.1 C30.1 C31.1 C32.1 C33.1 C34.1 C35.1 C36.1 C37.1 C38.1 C39.1 C41.1 C42.1 C44.1 C53.1 C54.1 C56.1 C57.1 C58.1 C59.1 C61.1 C62.1 C63.1 C65.1 C66.1 C67.1 C68.1 C69.1 C71.1 C72.1 C73.1 C200.1 C202.2 C204.1 C205.1 C207.2 C208.1 C210.1 C212.2 C214.1 C215.1 C217.2 C218.1 C220.1 C221.1 C222.1 C223.1 C234.1 C235.1 C237.1 C238.1 C239.1 C240.1 C241.1 C242.1 C244.1 C248.1 C250.1 C251.1 C252.1 C268.1 C269.1 C271.1 C272.1 C273.1 C274.1 C275.1 C276.1 C277.1 GND1.1(TP1) GND2.1 GND3.1 GND4.1 GND5.1(TP1) GND6.1(TP1) GND7.1(TP1) GND8.1 GND10.1 GND_SNS.1(TP1) GNDS1.1(TP1) GNDS2.1(TP1) GNDS3.1(TP1) GNDS_SBB0.1(TP1) GNDS_SBB1.1(TP1) GNDS_SBB2.1(TP1) GNDS_SBB3.1(TP1) J1.5 J1.6 J1.7 J1.8 J1.9 J1.10 J1.11 J2.6 J9.2 L3.1 L3.2 L6.1 L6.2 L7.1 L7.2 L8.1 L8.2 L9.1 L9.2 Q1.2(S) Q2.2(S) Q206.2(S) R3.2 R4.2 R6.2 R12.1 R17.2 R24.2 R28.2 R33.2 R52.1 R206.1 R208.2 R210.2 R211.2 R213.2 R226.1 R230.2 R231.2 R233.2 R234.2 R240.1 R243.2 R244.2 R245.2 R247.2 R252.1 R255.2 R257.2 R258.2 R260.2 R282.2 R287.2 R301.2 SW1.2 SW2.3 U1.A1 U1.D3 U2.1 U2.5 U2.10 U2.11 U2.13 U2.15 U2.25 U2.35 U2.47 U2.51 U3.2 U4.2 U5.5 U5.13 U7.1 U7.2 U7.3 U7.4 U205.C3 U205.D4 U209.15 U210.1 U210.2 U211.4 Y1.2 Y1.4
IN: C1.2 C2.1 C5.2 IN.1 IN_SNS.1(TP1) J5.1 J9.1 R8.1 R37.1 SW2.1 U1.D1
ISET_SBB0: R203.1 U205.D2
ISET_SBB1: R224.1 U205.D1
ISET_SBB2: R237.1 U205.C1
ISET_SBB3: R250.1 U205.C2
J3-5: J3.5 Q1.3 Q2.3 R8.2
LXA: L1.2 U1.D2
LXB: C4.2 L1.1 R34.1 U1.C3
NEN: J2.2 J3.2 J3.4 J3.6 U1.C2
NEN_EXT: NEN_EXT.1(TP1) R32.2 R33.1
NEN_FTDI: R31.1 U5.4
NIRQ: J2.3 NIRQ.1(TP1) R5.2 R27.2 U1.B2
NIRQ_FTDI: R19.1 U2.29
RST#: R14.2 U2.14
SBB0: B0_S.1(SIG) B0_SNS.1(TP1) C12.1 C14.2 C15.2 C56.2 C61.2 C65.2 C68.2 J4.4 J201.2 SBB0.1(TP1) U1.A3
SBB1: B1_S.1(SIG) B1_SNS.1(TP1) C11.2 C17.2 C57.2 C62.2 C66.2 C71.2 J203.2 SBB1.1(TP1) U1.A4
SBB2: B2_S.1(SIG) B2_SNS.1(TP1) C8.2 C18.2 C53.2 C58.2 C67.2 C72.2 J205.2 SBB2.1(TP1) U1.B4
SBB3: B3_S.1(SIG) B3_SNS.1(TP1) C6.2 C13.2 C54.2 C59.2 C63.2 C69.2 J207.2 SBB3.1(TP1) U1.C4
SCL: J2.4 R29.2 SCL.1(TP1) U1.B1
SCL_FTDI: R22.2 R53.2 R304.1 R306.1 U2.16 U5.10
SDA: J2.5 R30.2 SDA.1(TP1) U1.C1
SDA_FTDI: R21.2 R54.2 R303.1 R305.1 U2.17 U2.18 U5.9
UNNAMED_1_CAPNP_I203_2: C19.2 R34.2
UNNAMED_1_CL-SB-12B-1X_I99_2: J3.3 SW2.2
UNNAMED_1_DIOSCHOTTKY_I184_K: D1.C(K) J5.2
UNNAMED_1_EVQ-Q2XXXX_I7_3: J3.1 R37.2 SW1.3
UNNAMED_1_RESSMD_I163_1: R3.1 R7.1 R31.2
UNNAMED_1_RESSMD_I164_2: Q1.1 R7.2
UNNAMED_1_RESSMD_I188_1: Q2.1 R32.1
UNNAMED_2_CAPNP_I56_2: C234.2 R277.2 U210.3 U210.4
UNNAMED_2_CAPNP_I61_2: C235.2 R279.1 U210.5(VOUT_S) U210.6
UNNAMED_2_CAPNP_I79_2: C238.2 R281.2 R282.1 U209.12
UNNAMED_2_CAPNP_I84_2: C252.2 R301.1 R302.2 U209.6
UNNAMED_2_CAPNP_I95_2: C7.2 R1.2 R4.1 U209.5
UNNAMED_2_CAPNP_I101_2: C9.2 R2.2 R6.1 U209.11
UNNAMED_2_EKRESSMD_I66_2: C237.2 R286.2 U209.16(VDD)
UNNAMED_2_EKRESSMD_I73_2: R303.2 U209.14
UNNAMED_2_EKRESSMD_I74_2: R304.2 U209.13
UNNAMED_2_EKRESSMD_I91_1: AIN1.1(TP1) R302.1
UNNAMED_2_EKRESSMD_I96_1: AIN0.1(TP1) R1.1
UNNAMED_2_RESSMD_I67_2: Q205.1 Q206.3 R288.2
UNNAMED_2_RESSMD_I82_1: AIN7.1(TP1) R281.1
UNNAMED_2_RESSMD_I99_1: AIN6.1(TP1) R2.1
UNNAMED_4_AT24CS02_I136_SCL: R53.1 U7.6
UNNAMED_4_AT24CS02_I136_SDA: R54.1 U7.5
UNNAMED_4_AT24CS02_I136_VCC: C73.2 R20.2 U7.8
UNNAMED_4_AT24CS02_I136_WP: R52.2 U7.7(WP)
UNNAMED_4_FT2232H_I13_ACBUS4: U2.30 U5.7
UNNAMED_4_LED_I121_B: DS2.K(B) R28.1
UNNAMED_4_LED_I128_B: DS1.K(B) R18.1
UNNAMED_4_MAX3395E_I143_I: R18.2 R19.2 U5.8
UNNAMED_4_MAX3395E_I143_I_1: R26.2 R29.1 U5.1
UNNAMED_4_MAX3395E_I143_I_2: R25.2 R30.1 U5.2
UNNAMED_4_MAX3395E_I143_I_3: R27.1 U5.3
UNNAMED_4_MAX8512_I103_FB: R16.2 R17.1 U3.4
UNNAMED_4_MAX8512_I112_FB: R23.2 R24.1 U4.4
UNNAMED_6_CAPNP_I21_1: C203.1 R202.2 R205.1 U200.7(OUTB)
UNNAMED_6_CAPNP_I21_2: C203.2 R205.2 R208.1 R294.2 U200.6
UNNAMED_6_CAPNP_I22_2: C204.2 R206.2 R207.1 R293.1 U200.5
UNNAMED_6_CAPNP_I271_2: C208.2 R226.2 R229.1 R295.1 U201.5
UNNAMED_6_CAPNP_I277_1: C209.1 R223.2 R228.1 U201.7(OUTB)
UNNAMED_6_CAPNP_I277_2: C209.2 R228.2 R230.1 R296.2 U201.6
UNNAMED_6_CAPNP_I289_2: C248.2 R224.2 U201.3
UNNAMED_6_CAPNP_I307_2: C214.2 R240.2 R242.1 R297.1 U202.5
UNNAMED_6_CAPNP_I311_1: C213.1 R236.2 R239.1 U202.7(OUTB)
UNNAMED_6_CAPNP_I311_2: C213.2 R239.2 R243.1 R298.2 U202.6
UNNAMED_6_CAPNP_I323_2: C250.2 R237.2 U202.3
UNNAMED_6_CAPNP_I341_2: C218.2 R252.2 R254.1 R299.1 U203.5
UNNAMED_6_CAPNP_I345_1: C219.1 R249.2 R253.1 U203.7(OUTB)
UNNAMED_6_CAPNP_I345_2: C219.2 R253.2 R255.1 R300.2 U203.6
UNNAMED_6_CAPNP_I357_2: C251.2 R250.2 U203.3
UNNAMED_6_CAPNP_I359_2: C200.2 R203.2 U200.3
UNNAMED_6_EKCAPNP_I10_1: C201.1 R202.1 U200.2
UNNAMED_6_EKCAPNP_I10_2: C201.2 R201.1
UNNAMED_6_EKCAPNP_I203_2: C223.2 U205.D3
UNNAMED_6_EKCAPNP_I237_2: C239.2 J201.1 Q200.5 Q200.6 Q200.7 Q200.8 R212.1
UNNAMED_6_EKCAPNP_I261_2: C240.2 J203.1 Q201.5 Q201.6 Q201.7 Q201.8 R227.1
UNNAMED_6_EKCAPNP_I287_1: C206.1 R223.1 U201.2
UNNAMED_6_EKCAPNP_I287_2: C206.2 R222.1
UNNAMED_6_EKCAPNP_I298_2: C241.2 J205.1 Q202.5 Q202.6 Q202.7 Q202.8 R246.1
UNNAMED_6_EKCAPNP_I321_1: C211.1 R236.1 U202.2
UNNAMED_6_EKCAPNP_I321_2: C211.2 R235.1
UNNAMED_6_EKCAPNP_I332_2: C242.2 J207.1 Q203.5 Q203.6 Q203.7 Q203.8 R259.1
UNNAMED_6_EKCAPNP_I355_1: C216.1 R249.1 U203.2
UNNAMED_6_EKCAPNP_I355_2: C216.2 R248.1
UNNAMED_6_EKCAPNP_I377_1: C270.1 U211.3
UNNAMED_6_EKCAPNP_I377_2: C270.2 U211.6
UNNAMED_6_EKCAPNP_I423_2: C273.2 R289.2 U211.5
UNNAMED_6_EKRESSMD_I42_2: Q200.1 Q200.2 Q200.3(S3) R207.2 R211.1 VIL_SBB0.1(TP1)
UNNAMED_6_EKRESSMD_I99_1: R201.2 R204.1 U200.1
UNNAMED_6_EKRESSMD_I99_2: J200.2 R204.2
UNNAMED_6_EKRESSMD_I207_2: R214.2 U205.C4
UNNAMED_6_EKRESSMD_I222_2: R283.2 U205.D5
UNNAMED_6_EKRESSMD_I273_2: Q201.1 Q201.2 Q201.3(S3) R229.2 R233.1 VIL_SBB1.1(TP1)
UNNAMED_6_EKRESSMD_I278_1: R222.2 R225.1 U201.1
UNNAMED_6_EKRESSMD_I278_2: J202.1 R225.2
UNNAMED_6_EKRESSMD_I306_2: Q202.1 Q202.2 Q202.3(S3) R242.2 R245.1 VIL_SBB2.1(TP1)
UNNAMED_6_EKRESSMD_I313_1: R235.2 R238.1 U202.1
UNNAMED_6_EKRESSMD_I313_2: J204.1 R238.2
UNNAMED_6_EKRESSMD_I340_2: Q203.1 Q203.2 Q203.3(S3) R254.2 R258.1 VIL_SBB3.1(TP1)
UNNAMED_6_EKRESSMD_I347_1: R248.2 R251.1 U203.1
UNNAMED_6_EKRESSMD_I347_2: J206.1 R251.2
UNNAMED_6_EKRESSMD_I450_2: R305.2 U205.B4
UNNAMED_6_EKRESSMD_I451_2: R306.2 U205.B5
UNNAMED_6_HEADER2P_I442_1: J200.1 Q200.4 R210.1
UNNAMED_6_HEADER2P_I444_2: J202.2 Q201.4 R231.1
UNNAMED_6_HEADER2P_I446_2: J204.2 Q202.4 R244.1
UNNAMED_6_HEADER2P_I448_2: J206.2 Q203.4 R257.1
USB_DM: J1.2 R10.1
USB_DP: J1.3 R11.1
VADC: Q205.2(S) R277.1 R286.1 R288.1
VLOGIC: C44.2 J2.1 J4.1 J4.3 J4.5 R5.1 R25.1 R26.1 U5.6 U5.12(VL)
VPHY: C26.2 L5.2 U2.4
VPLL: C27.2 L4.2 U2.9
VREGOUT: C28.2 R15.2 U2.49(VREGOUT)
VUSB: C21.2 C22.2 C29.2 C41.2 C202.1 C207.1 C212.1 C217.1 D1.A L2.2 Q205.3 Q206.1 R287.1 U3.1 U3.3(SHDN*) U4.1 U4.3(SHDN*) U200.8 U201.8 U202.8 U203.8 VUSB.1(TP1)

Pads without a net: J1 4; SW1 1 4; U2 19 21 22 23 24 26 27 28 32 33 34 36 38 39 40 41 43 44 45 46 48 52 53 54 55 57 58 59 60 61 62 63; U205 A1 A2 B1 B2 C5; U209 2 3 4

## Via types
v1: diameter 0.457, hole 0.203, TOP to BOTTOM, 357 vias
v2: diameter 0.254, hole 0.127, TOP to BOTTOM, 12 vias
v3: diameter 0.254, hole 0.127, TOP to INTERNAL2, 33 vias

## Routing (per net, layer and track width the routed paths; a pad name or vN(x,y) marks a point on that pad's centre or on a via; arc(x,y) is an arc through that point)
+1.8V: length 75.2
  TOP w0.381: v1(12.04,58.5) 21.23,58.5 v1(22.15,59.43) 28.37,59.43 30.88,61.94 v1(32.3,61.94)
  TOP w0.508: v1(32.3,70.35) J4.6
  INTERNAL3 w0.381: v1(12.04,58.5) 12.04,51.85 12.03,51.83 12.03,51.4 12.04,51.39 12.04,47.4 12.01,47.36 v1(12.01,45.29) 11.99,45.27 v1(11.99,43.09)
  INTERNAL3 w0.508: v1(32.3,70.35) 32.3,69.61 32.3,69.61 v1(32.3,61.94)
  BOTTOM w0.254: C37.2 21.81,44.41 21.77,44.45 U2.37 ; U2.64 12.9,55.62 12.66,55.38 C32.2 12.08,56.33 C34.2 ; 22.15,60.02 22.15,60.02 22.15,59.44 21.77,59.06 U2.12
  BOTTOM w0.381: v1(22.15,59.43) 22.15,60.02 C30.2 ; v1(12.01,45.29) 12,45.3 R15.1 ; C36.2 34.92,63.22 34.84,63.14 U3.5 33.84,62.07 33.67,61.89 R16.1 32.93,61.94 v1(32.3,61.94) ; C34.2 12.07,56.99 12.04,57.02 v1(12.04,58.5) ; v1(11.99,43.09) 14.4,43.09 14.51,43.2 20.59,43.2 21.17,43.77 C37.2
+3.3V: length 241.3
  TOP w0.381: DS2.A 36.08,50.88 v1(35.06,50.88) DS1.A
  TOP w0.508: v1(12.71,51.62) v1(20.13,51.62) ; v1(23.11,64.27) 23.1,64.28 v1(17.37,64.28)
  INTERNAL3 w0.381: v1(35.06,50.88) 35.07,50.87 ; 35.07,50.87 35.07,56.47 35.08,56.47 v1(35.08,57.15) ; 35.07,50.87 35.07,46.35 v1(35.09,46.34) ; v1(27.44,54.12) v1(27.44,57.13) ; v1(62.12,15.82) v1(62.12,25.85) v1(62.12,37.86) 63.52,39.26 v1(63.52,50.75)
  INTERNAL3 w0.508: v1(27.11,38.15) v1(27.11,41.24) 27.11,48.28 v1(27.41,48.58) 27.41,49.31 27.44,49.34 v1(27.44,54.12) ; v1(62.56,65.73) v1(62.56,62.32) 62.56,60.77 63.52,59.81 v1(63.52,50.75) ; v1(41.58,65.28) 41.58,68.26 40.87,68.97 J4.2 ; v1(35.08,57.15) v1(35.08,65.31) ; v1(22.16,41.21) 22.12,41.25 22.12,41.89 v1(20.18,43.84) 20.18,44.58 20.13,44.62 v1(20.13,51.62)
  BOTTOM w0.203: R22.1 25.47,37.72 25.22,37.48 24.8,37.48 24.59,37.28 24.59,36.88 C16.2 24.04,36.87 23.98,36.82 U5.11
  BOTTOM w0.254: U205.A5 41.48,49.14 41.71,49.38 ; 41.71,49.38 41.98,49.12 U205.A4 ; 41.71,49.38 C221.2 C222.2 42.48,49.06 U205.A3 U205.B3 ; R300.1 60.97,15.78 R299.2 ; U2.50 12.85,48.62 12.59,48.88 C25.2 ; U2.20 v1(27.44,54.12) ; U2.31 27.37,48.62 v1(27.41,48.58) ; C35.2 19.25,44.53 19.27,44.54 U2.42 ; R295.2 61.13,37.87 61.11,37.86 ; R294.1 62.75,50.75 R293.2 v1(63.52,50.75) ; U2.56 v1(12.71,51.62) 12.71,51.62 C33.2 ; R298.1 61,27.16 R297.2
  BOTTOM w0.381: R22.1 v1(27.11,38.15) ; R298.1 61.33,25.85 v1(62.12,25.85) ; v1(27.44,54.12) 27.48,54.08 C39.2 ; C42.2 35.08,55.45 35,55.37 U4.5 33.91,54.29 33.84,54.22 R23.1 ; C25.2 12.01,50.89 11.97,50.92 C33.2 ; R14.1 v1(23.11,64.27) ; v1(35.06,50.88) 40.01,50.88 41.44,49.46 C221.2 ; R214.1 38.76,46.46 R283.1 36.06,46.46 35.94,46.34 v1(35.09,46.34) ; R296.1 61.11,37.86 v1(62.12,37.86) ; v1(27.44,57.13) 34.38,57.13 34.4,57.15 v1(35.08,57.15) ; R21.1 v1(22.16,41.21) 22.2,41.24 v1(27.11,41.24) ; R289.1 62.5,62.25 v1(62.56,62.32) ; 53.29,64.29 53.38,64.21 C268.2 53.37,63.51 C269.2 54.11,62.68 54.52,62.27 U211.2 ; R299.2 61.01,15.82 v1(62.12,15.82) ; 46.61,65.31 46.62,65.3 R20.1 ; C35.2 19.26,43.84 v1(20.18,43.84) ; v1(27.41,48.58) 27.99,48.58 C38.2 C31.2
  BOTTOM w0.508: 41.68,65.31 41.65,65.28 v1(41.58,65.28) ; 41.68,65.31 46.19,65.31 46.19,65.31 52.28,65.31 52.81,64.78 ; 41.68,65.31 v1(35.08,65.31) 24.15,65.31 v1(23.11,64.27) ; 23.11,63.26 23.1,63.27 L4.1 ; v1(62.56,65.73) 53.76,65.73 52.81,64.78 ; 52.81,64.78 53.29,64.29 ; L5.1 v1(17.37,64.28) ; C42.2 v1(35.08,57.15)
PVDD: length 28.6
  INTERNAL3 w0.203: v1(35.07,24.46) 35.07,23.85 37.2,21.72 38.68,21.72 40.53,19.88 PVDD.1
  BOTTOM w0.381: v1(35.07,24.46) 32.87,24.46 32.86,24.47 32.46,24.47 31.86,25.08 R9.1
VCC_USB: length 3.6
  TOP w0.381: J1.1 21.91,72.1
  TOP w0.457: 21.91,72.1 21.91,70.4 22.56,69.75 L2.1
VDD: length 36.5
  TOP w0.254: U1.A2 32.66,27.1 32.38,27.39 C10.2
  TOP w0.381: 31.79,29.44 32.24,28.98 v1(32.24,28.96) 32.38,28.82 C10.2
  TOP w0.635: VDD.1 6.73,34.69 8.12,36.08 12.66,36.08 13.67,35.06 26.16,35.06 31.79,29.44
  BOTTOM w0.381: v1(32.24,28.96) 32.24,28.28 31.86,27.9 R9.2
VSS: length 58.8
  INTERNAL3 w0.254: v1(53.17,16.45) v1(53.17,26.18) 53.17,35.88 v1(51.66,37.39)
  INTERNAL3 w0.381: v1(51.66,37.39) 51.66,46.21 54.36,48.91 v1(54.36,51.05) 53.41,52 v1(53.41,60.36)
  BOTTOM w0.254: U203.4 53.18,16.44 v1(53.17,16.45) 53.17,17.01 C277.2 ; C276.2 53.17,26.69 v1(53.17,26.18) 53.08,26.09 U202.4 ; C274.2 55.07,50.34 55.06,50.34 U200.4
  BOTTOM w0.381: v1(53.41,60.36) C272.2 53.41,61.82 ; U211.1 54.17,61.32 53.78,61.71 53.52,61.71 53.41,61.82 ; C271.2 53.41,61.82 ; v1(54.36,51.05) 55.06,51.05 C274.2 ; U201.4 52.3,36.75 v1(51.66,37.39) 51.66,38.11 51.71,38.15 C275.2
ADC_REF: length 3.5
  BOTTOM w0.254: R279.2 76.15,58.56 75.83,58.87 C244.2
  BOTTOM w0.381: U209.1 74.86,58.88 C244.2
ADC_SBB0: length 19.4
  TOP w0.381: R212.2 70.88,47.78 v1(69.8,47.78)
  INTERNAL3 w0.381: v1(69.07,56.66) 69.07,48.52 v1(69.8,47.78)
  BOTTOM w0.381: R213.1 67.5,56.66 C205.2 69.07,56.66 v1(69.07,56.66) 69.72,57.31 U209.7
ADC_SBB1: length 34.8
  TOP w0.381: v1(70.79,34.18) 75.3,34.18 75.64,34.52 R227.2
  INTERNAL3 w0.381: v1(66.55,56.85) 66.55,47.21 70.79,42.98 v1(70.79,34.18)
  BOTTOM w0.381: v1(66.55,56.85) 66.62,56.92 C210.2 R234.1 67.27,59.04 67.43,58.88 U209.8
ADC_SBB2: length 48
  TOP w0.381: v1(71.55,28.28) 72.35,28.28 73.08,27.55 R246.2
  INTERNAL3 w0.381: v1(67.34,65.44) 67.34,65.2 67.36,65.18 67.36,47.58 71.55,43.4 v1(71.55,28.28)
  BOTTOM w0.381: v1(67.34,65.44) C215.2 R247.1 67.47,64.26 67.68,64.48 U209.9
ADC_SBB3: length 62.6
  TOP w0.381: v1(76.14,16.99) 76.61,16.99 R259.2
  INTERNAL3 w0.381: v1(67.26,68.45) 68.1,67.62 68.1,47.97 72.27,43.8 72.27,18.75 74.03,16.99 v1(76.14,16.99)
  BOTTOM w0.381: v1(67.26,68.45) 67.27,68.44 R260.1 67.3,67.64 C220.2 67.3,66.72 68.07,65.95 69.31,65.95 69.72,65.55 U209.10
BST: length 0.6
  TOP w0.152: U1.B3 33.35,26.33 v2(33.35,26.33)
  BOTTOM w0.381: C4.1 33.37,26.35 33.35,26.33 v2(33.35,26.33)
FTDI_DM: length 12.5
  TOP w0.203: R10.2 21.11,68.19 20.58,67.67 v1(18.97,67.67)
  INTERNAL3 w0.203: v1(18.97,67.67) v1(18.97,62.55)
  BOTTOM w0.203: v1(18.97,62.55) 18.97,61.96 19.27,61.67 U2.7
FTDI_DP: length 11.3
  TOP w0.254: v1(19.56,68.17) 20.23,68.17 R11.2
  INTERNAL3 w0.203: v1(19.56,68.17) 19.56,67.59 19.65,67.51 v1(19.65,62.58)
  BOTTOM w0.203: U2.8 19.77,61.87 19.65,61.99 v1(19.65,62.58)
FTDI_OSCI: length 8.7
  BOTTOM w0.254: 15.21,59.89 15.21,59.85 16.19,58.86 16.51,58.86 16.77,58.61 U2.2 ; 15.21,59.89 R13.1 ; 15.21,59.89 14.7,59.38 12.48,59.38 12.07,59.79 C23.2 11.95,60.13 Y1.1
FTDI_OSCO: length 10.2
  BOTTOM w0.254: Y1.3 14.54,63.91 14.55,63.91 C24.2 15.53,63.91 16.06,63.38 16.06,62.41 15.21,61.56 R13.2 15.72,60.92 15.98,60.67 15.98,59.68 16.38,59.28 16.88,59.28 17.27,58.9 U2.3
FTDI_REF: length 2.4
  BOTTOM w0.254: U2.6 18.77,59.23 18.58,59.42 R12.2
GROUND: length 522.6
  TOP w0.203: v1(31.49,28.55) 31.48,28.54 C10.1 31.48,27.33 U1.A1
  TOP w0.254: Q1.2 14.58,62.36 v1(14.58,62.36) 14.88,62.06 R3.2
  TOP w0.381: 32.34,2.74 L3.2 24.6,2.74 24.59,2.73 L6.1 21,2.73 20.93,2.66 L7.1 16.43,2.66 16.33,2.76 L8.2 12.84,2.76 12.74,2.66 L9.2 ; 32.28,4.32 L3.1 24.6,4.32 24.59,4.33 L6.2 21,4.33 20.43,4.89 L7.2 16.43,4.89 16.33,4.79 L8.1 12.84,4.79 12.74,4.89 L9.1 ; C239.1 75.54,46.7 v1(75.44,46.6) ; v1(22.27,55.54) 21.39,55.54 SW1.2 ; R28.2 v1(36.25,49.23) ; v1(32.63,29.59) 32.77,29.45 C14.1 ; 23.81,72.33 23.91,72.43 ; SW2.3 2.96,58.75 v1(3.67,59.46) ; Q2.2 v1(13.15,67.86) ; v1(14.78,64.9) 14.8,64.92 R33.2
  TOP w0.508: J1.6 23.88,72.43 J1.10 J1.8 J1.9 J1.11 17.28,72.43 J1.7
  INTERNAL2 w0.089: 33.16,26.07 33.51,26.07
  INTERNAL3 w0.203: GND_SNS.1 43.7,2.56 40.99,5.27 40.99,18.66 40.98,18.67 40.98,20.08 38.86,22.19 37.62,22.19 v1(36.45,23.36) ; v1(53.78,4.95) 50.62,4.95 50.18,5.39 45.67,5.39 42.56,8.49 42.56,20.37 39.43,23.5 38.24,23.5 37.29,24.45 v1(36.89,24.45) ; v1(36.51,28.79) 37.09,28.79 37.2,28.89 39.21,28.89 44.97,23.14 44.97,9.49 47.02,7.43 61.22,7.43 62.04,6.62 v1(62.98,6.62) ; v1(56.16,6.38) 46.48,6.38 43.67,9.19 43.67,21.34 40.41,24.6 38.43,24.6 36.74,26.29 v2(36.74,27.2) ; v1(69.45,6.48) 68.52,6.48 66.53,8.47 47.96,8.47 46.14,10.29 46.14,23.89 40.31,29.72 33.65,29.72 33.53,29.59 v1(32.63,29.59)
  INTERNAL3 w0.381: v1(74.97,14.75) 76.37,16.14 82.74,16.14 83.83,15.05 83.83,4.47 GNDS_SBB3.1 ; v1(75.09,25.54) 75.57,26.01 83.77,26.01 93.27,16.52 GNDS_SBB2.1 ; v1(75.03,36.17) 76.65,37.79 86.42,37.79 92.18,32.03 92.18,31.34 GNDS_SBB1.1 ; v1(75.38,49.45) 76.41,49.45 77.28,50.33 86.74,50.33 90.56,46.5 90.56,46.34 GNDS_SBB0.1
  BOTTOM w0.152: U205.C3 42.65,47.23 v2(42.65,47.23)
  BOTTOM w0.203: v1(69.45,6.48) 70.33,6.48 B0_S.3
  BOTTOM w0.254: B2_S.3 56.32,6.54 v1(56.16,6.38) ; v1(62.98,6.62) 63.93,6.62 B1_S.3 ; C276.1 51.75,26.73 v1(51.71,26.77) 51.56,26.92 49.5,26.92 49.28,26.7 C250.1 ; C30.1 v1(21.45,60.92) 21.27,60.74 C27.1 21.27,59.47 21,59.2 ; R240.1 C214.1 v1(55.94,26.73) ; C33.1 v1(10.57,51.62) ; U2.11 21.27,58.93 21,59.2 ; B3_S.2 53.79,5.06 53.78,5.05 v1(53.78,4.95) ; C24.1 15.23,63.01 v1(14.58,62.36) 14.19,62.36 Y1.4 13.55,60.64 12.97,60.06 C23.1 ; C34.1 11.18,56.33 C32.1 v1(10.55,55.38) ; U2.10 20.77,58.96 21,59.2 ; C35.1 17.64,43.84 17.63,43.84 v1(16.77,43.84) U2.47 ; v1(12.76,49.45) 13.1,49.12 U2.51 ; R233.2 75.01,36.06 75.01,37.09 74.71,37.39 71.37,37.39 71.02,37.03 R230.2 ; R211.2 75.4,50.81 75.13,51.08 72.33,51.08 70.78,49.53 R208.2 ; C39.1 v1(29.98,54.08) ; v1(26.17,36.87) C16.1 25.49,36.87 C44.1 ; v1(58.29,51.98) R206.1 58.88,51.06 C204.1 ; U210.2 84.68,56.95 84.99,57.25 84.99,59.73 83.69,61.03 75.09,61.03 72.89,63.22 U209.15 ; C223.1 41.79,45.46 41.87,45.54 41.87,45.55 41.98,45.65 U205.D4 ; v1(56.23,33.22) C207.2 ; U2.35 22.77,44.46 22.71,44.41 C37.1 v1(23.53,43.77) ; R12.1 v1(18.58,61.37) ; v1(51.32,51.21) 51.34,51.2 C200.1 ; U2.15 v1(23.27,55.57) ; U2.1 v1(13.92,57.67) ; U5.13 U5.5 v1(17.21,36.82) ; R245.2 75.01,26.64 74.78,26.86 74.18,26.86 74.17,26.85 R243.2 ; C277.1 51.22,17.06 v1(51.21,17.04) ; Y1.2 v1(10.66,63.91) ; C25.1 11.11,48.87 C28.1 10.64,47.92 v1(10.6,47.96) ; U2.5 v1(18.27,55.5) ; C38.1 C31.1 ; U2.25 v1(28.29,51.62) ; C212.2 v1(56.91,20.4) ; C217.2 v1(56.3,11.73) ; R258.2 75.01,15.82 74.74,16.08 72.35,16.08 70.06,18.38 R255.2 ; U2.13 v1(22.27,55.54)
  BOTTOM w0.381: v1(64.73,56.53) 65.51,55.76 R213.2 68.37,55.76 C205.1 ; C269.1 v1(51.56,62.68) ; C269.1 52.47,63.51 C268.1 ; C269.1 52.49,62.66 C271.1 52.49,61.03 C272.1 v1(51.61,61) ; v1(48.62,62.28) 48.64,62.26 C73.1 ; v1(64.72,59.04) R234.2 C210.1 ; v1(39.29,62.67) C29.1 39.11,61.85 38.68,61.42 U3.2 ; R257.2 87.76,18.91 ; C252.1 71.19,54.88 R301.2 v1(71.62,54.87) 72.04,54.87 R4.2 72.05,55.69 C7.1 ; v1(36.15,63.25) 36.14,63.25 C36.1 ; C235.1 v1(82.45,59.49) ; v1(87.87,18.92) 87.84,18.92 ; v1(74.31,67.84) C238.1 73.5,66.75 R282.2 73.51,66.08 72.89,65.47 U209.15 ; v1(43.85,50.36) C222.1 C221.1 ; v1(68.86,68.47) 68.86,67.92 R6.2 68.97,67.79 C9.1 ; C26.1 v1(16.86,60.54) ; v1(87.83,29.43) 87.09,29.43 R244.2 ; v1(36.32,55.48) 36.3,55.5 C42.1 ; C234.1 v1(82.69,54.41) ; U4.2 38.3,53.64 38.62,53.96 39.33,53.96 C41.1 ; v1(66.29,63.43) 65.93,63.79 R247.2 C215.1 ; C220.1 66.4,67.33 66.37,67.36 R260.2 66.39,67.68 v1(66.39,68.41) ; v1(30.69,53.3) 30.69,53.25 30.69,53.25 31.23,53.25 R24.2 ; U7.4 U7.3 U7.2 U7.1 v1(48.3,55.12) ; v1(60.72,63.18) C273.1 59.29,63.18 59.25,63.22 U211.4 ; U210.1 v1(83.7,58.7) ; v1(84.28,61.96) R287.2 83.42,62.59 82.79,61.96 Q206.2 ; C274.1 v1(56.65,51.06) ; R52.1 v1(45.4,64.48) ; C237.1 v1(75.2,62.99)
  BOTTOM w0.508: B0_S.2 B0_S.3 ; C41.1 v1(39.37,54.95) ; B2_S.2 B2_S.3 ; B3_S.2 B3_S.3 ; B1_S.2 B1_S.3
  vias: v1(7.57,18.13) v1(10.75,13.71) v1(10.78,12.82) v1(11.79,13.74) v1(11.81,12.84) v1(12.74,13.74) v1(12.77,12.87) v1(16.96,71.06) v1(17.86,71.04) v1(18.8,71.04) v1(23.82,71.33) v1(23.87,39.74) v1(24.87,72.34) v1(24.88,71.35) v1(25.88,72.34) v1(25.87,71.35) v1(28.93,54.99) v1(28.92,41.27) v1(40.27,44.76) v1(49.56,38.92) v1(55.67,36) v1(72.78,49.16) v1(73.45,49.57) v1(73.48,48.73) v1(73.69,34.86) v1(74.45,34.85) v1(75.2,34.86) v1(76.3,25.2) v1(76.32,24.61) v1(76.58,14.78) v1(76.58,13.93) v1(87.06,40.88) v1(88.05,51.43) v1(94.34,17.22) v1(94.43,12.34) v3(33.17,24.79) v3(33.17,24.23) v3(33.34,22.98) v3(33.51,24.23) v3(33.71,23.84) v3(33.72,23.46) v3(33.73,22.99) v3(34.14,29.39) v3(34.11,23.45) v3(34.12,22.98) v3(34.15,28.97) v3(34.54,29.39) v3(34.55,28.97) v3(34.52,23.44) v3(34.53,22.97) v3(34.96,29.39) v3(34.97,28.97) v3(35.06,23.43) v3(35.07,22.96) v3(35.39,29.39) v3(35.39,28.97) v3(35.6,23.44) v3(35.6,22.97) v3(35.8,29.39) v3(35.81,28.97) v3(35.76,24.51) v3(35.75,24.09) v3(36.18,24.79) v3(36.17,24.33) v3(36.17,23.82) v3(36.4,27.2) v3(36.43,25.95) v3(36.73,25.95)
